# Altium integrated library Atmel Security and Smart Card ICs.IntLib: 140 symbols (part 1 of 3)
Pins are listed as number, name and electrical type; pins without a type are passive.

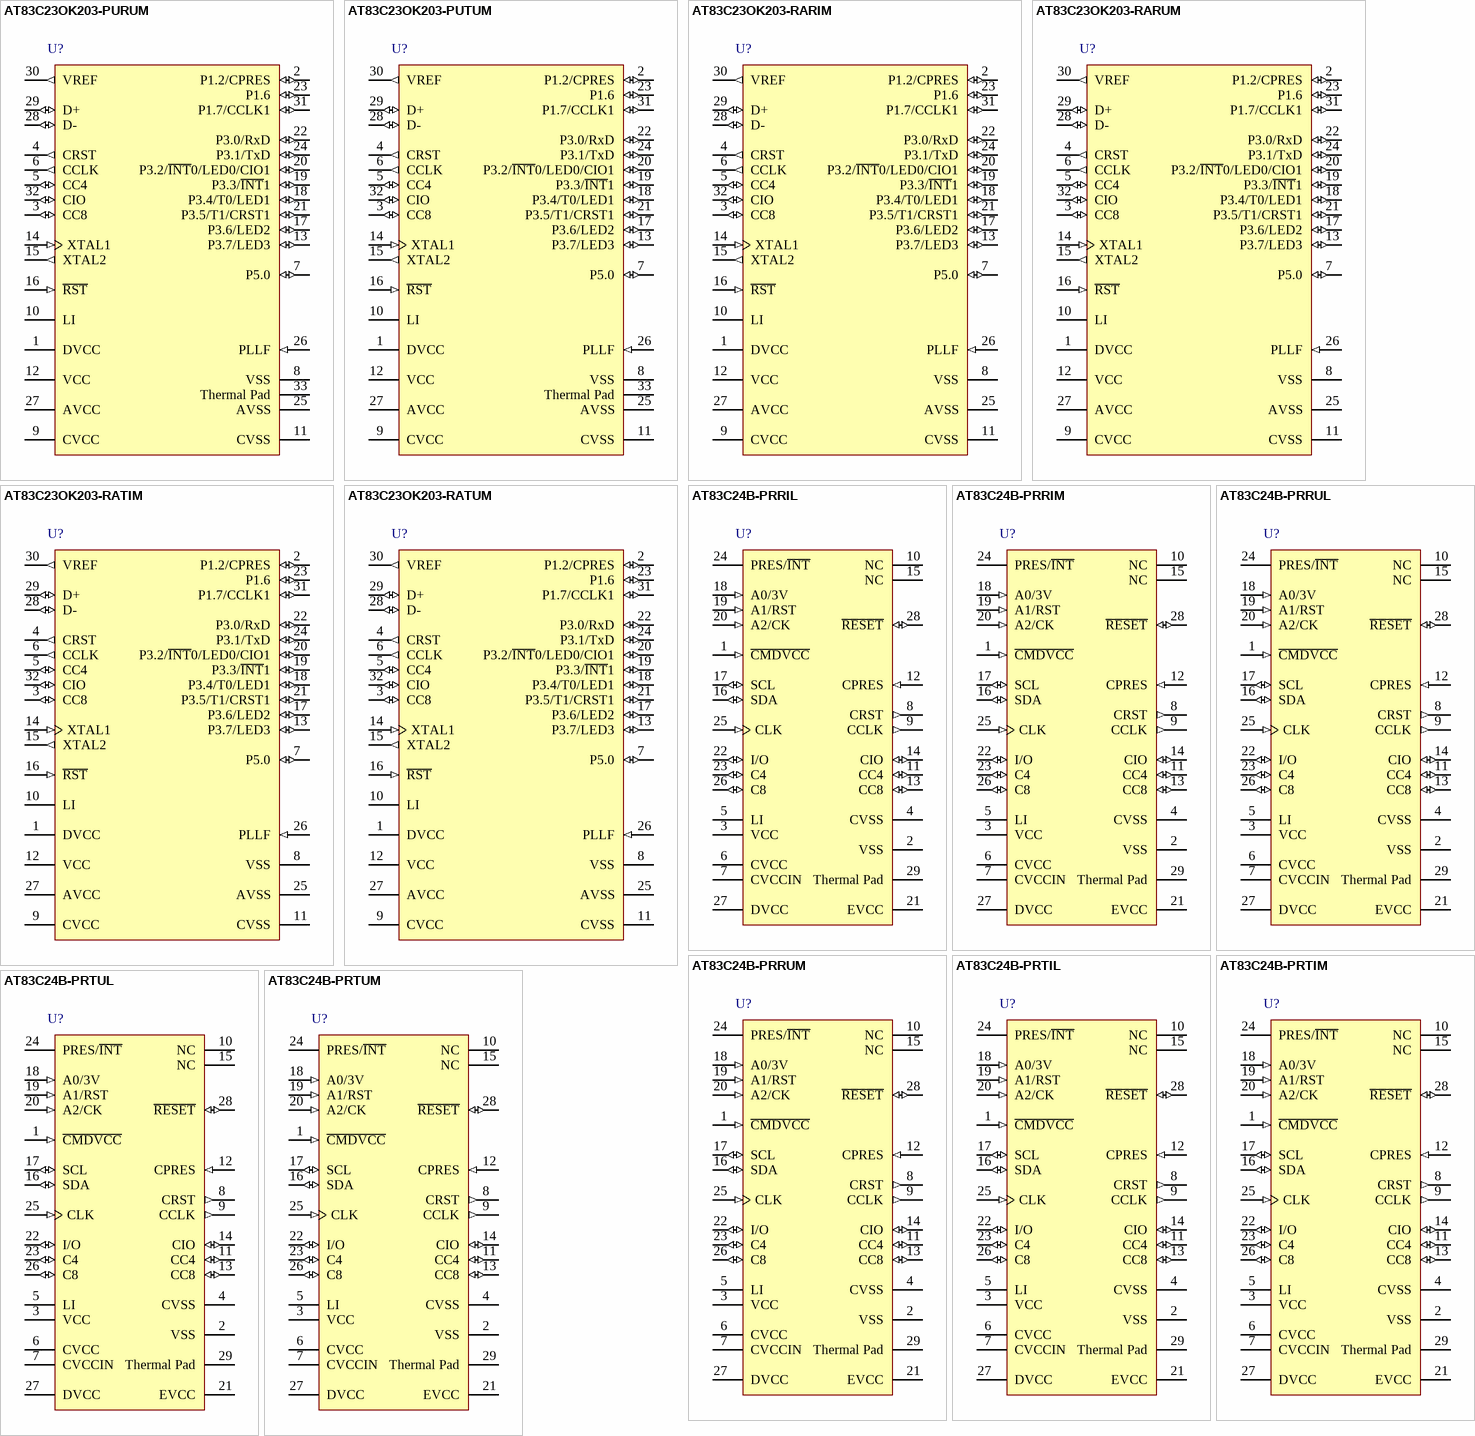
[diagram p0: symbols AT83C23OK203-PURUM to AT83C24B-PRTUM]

## AT83C23OK203-PURUM
designator U?
CardMan® Smart@Link Smart Card Interface, 32-Pin QFN Pkg, Industrial, Tape and Reel, Pb-Free
footprint QFN32_N (QFN, 32-Leads, Body 7x7 mm, Pitch 0.65mm, IPC Medium Density)
footprint QFN32_L (QFN, 32-Leads, Body 7x7 mm, Pitch 0.65mm, IPC High Density)
footprint QFN32_M (QFN, 32-Leads, Body 7x7 mm, Pitch 0.65mm, IPC Low Density)
pins: 1 DVCC (power), 2 P1.2/CPRES (io), 3 CC8 (io), 4 CRST (out), 5 CC4 (io), 6 CCLK (out), 7 P5.0 (io), 8 VSS (power), 9 CVCC (power), 10 LI (power), 11 CVSS (power), 12 VCC (power), 13 P3.7/LED3 (io), 14 XTAL1 (in), 15 XTAL2 (out), 16 ~{RST} (in), 17 P3.6/LED2 (io), 18 P3.4/T0/LED1 (io), 19 P3.3/~{INT}1 (io), 20 P3.2/~{INT}0/LED0/CIO1 (io), 21 P3.5/T1/CRST1 (io), 22 P3.0/RxD (io), 23 P1.6 (io), 24 P3.1/TxD (io), 25 AVSS (power), 26 PLLF (in), 27 AVCC (power), 28 D- (io), 29 D+ (io), 30 VREF (out), 31 P1.7/CCLK1 (io), 32 CIO (io), 33 Thermal Pad (power)

## AT83C23OK203-PUTUM
designator U?
CardMan® Smart@Link Smart Card Interface, 32-Pin QFN Pkg, Industrial, Tray, Pb-Free
footprint QFN32_N (QFN, 32-Leads, Body 7x7 mm, Pitch 0.65mm, IPC Medium Density)
footprint QFN32_L (QFN, 32-Leads, Body 7x7 mm, Pitch 0.65mm, IPC High Density)
footprint QFN32_M (QFN, 32-Leads, Body 7x7 mm, Pitch 0.65mm, IPC Low Density)
pins: 1 DVCC (power), 2 P1.2/CPRES (io), 3 CC8 (io), 4 CRST (out), 5 CC4 (io), 6 CCLK (out), 7 P5.0 (io), 8 VSS (power), 9 CVCC (power), 10 LI (power), 11 CVSS (power), 12 VCC (power), 13 P3.7/LED3 (io), 14 XTAL1 (in), 15 XTAL2 (out), 16 ~{RST} (in), 17 P3.6/LED2 (io), 18 P3.4/T0/LED1 (io), 19 P3.3/~{INT}1 (io), 20 P3.2/~{INT}0/LED0/CIO1 (io), 21 P3.5/T1/CRST1 (io), 22 P3.0/RxD (io), 23 P1.6 (io), 24 P3.1/TxD (io), 25 AVSS (power), 26 PLLF (in), 27 AVCC (power), 28 D- (io), 29 D+ (io), 30 VREF (out), 31 P1.7/CCLK1 (io), 32 CIO (io), 33 Thermal Pad (power)

## AT83C23OK203-RARIM
designator U?
CardMan® Smart@Link Smart Card Interface, 32-Pin QFP Pkg, Industrial, Tape and Reel
footprint LQFP32_N (Thin QFP, 32-Leads, Body 7x7mm, Pitch 0.8mm, IPC Medium Density)
footprint LQFP32_L (Thin QFP, 32-Leads, Body 7x7mm, Pitch 0.8mm, IPC High Density)
footprint LQFP32_M (Thin QFP, 32-Leads, Body 7x7mm, Pitch 0.8mm, IPC Low Density)
pins: 1 DVCC (power), 2 P1.2/CPRES (io), 3 CC8 (io), 4 CRST (out), 5 CC4 (io), 6 CCLK (out), 7 P5.0 (io), 8 VSS (power), 9 CVCC (power), 10 LI (power), 11 CVSS (power), 12 VCC (power), 13 P3.7/LED3 (io), 14 XTAL1 (in), 15 XTAL2 (out), 16 ~{RST} (in), 17 P3.6/LED2 (io), 18 P3.4/T0/LED1 (io), 19 P3.3/~{INT}1 (io), 20 P3.2/~{INT}0/LED0/CIO1 (io), 21 P3.5/T1/CRST1 (io), 22 P3.0/RxD (io), 23 P1.6 (io), 24 P3.1/TxD (io), 25 AVSS (power), 26 PLLF (in), 27 AVCC (power), 28 D- (io), 29 D+ (io), 30 VREF (out), 31 P1.7/CCLK1 (io), 32 CIO (io)

## AT83C23OK203-RARUM
designator U?
CardMan® Smart@Link Smart Card Interface, 32-Pin QFP Pkg, Industrial, Tape and Reel, Pb-Free
footprint LQFP32_N (Thin QFP, 32-Leads, Body 7x7mm, Pitch 0.8mm, IPC Medium Density)
footprint LQFP32_L (Thin QFP, 32-Leads, Body 7x7mm, Pitch 0.8mm, IPC High Density)
footprint LQFP32_M (Thin QFP, 32-Leads, Body 7x7mm, Pitch 0.8mm, IPC Low Density)
pins: 1 DVCC (power), 2 P1.2/CPRES (io), 3 CC8 (io), 4 CRST (out), 5 CC4 (io), 6 CCLK (out), 7 P5.0 (io), 8 VSS (power), 9 CVCC (power), 10 LI (power), 11 CVSS (power), 12 VCC (power), 13 P3.7/LED3 (io), 14 XTAL1 (in), 15 XTAL2 (out), 16 ~{RST} (in), 17 P3.6/LED2 (io), 18 P3.4/T0/LED1 (io), 19 P3.3/~{INT}1 (io), 20 P3.2/~{INT}0/LED0/CIO1 (io), 21 P3.5/T1/CRST1 (io), 22 P3.0/RxD (io), 23 P1.6 (io), 24 P3.1/TxD (io), 25 AVSS (power), 26 PLLF (in), 27 AVCC (power), 28 D- (io), 29 D+ (io), 30 VREF (out), 31 P1.7/CCLK1 (io), 32 CIO (io)

## AT83C23OK203-RATIM
designator U?
CardMan® Smart@Link Smart Card Interface, 32-Pin QFP Pkg, Industrial, Tray
footprint LQFP32_N (Thin QFP, 32-Leads, Body 7x7mm, Pitch 0.8mm, IPC Medium Density)
footprint LQFP32_L (Thin QFP, 32-Leads, Body 7x7mm, Pitch 0.8mm, IPC High Density)
footprint LQFP32_M (Thin QFP, 32-Leads, Body 7x7mm, Pitch 0.8mm, IPC Low Density)
pins: 1 DVCC (power), 2 P1.2/CPRES (io), 3 CC8 (io), 4 CRST (out), 5 CC4 (io), 6 CCLK (out), 7 P5.0 (io), 8 VSS (power), 9 CVCC (power), 10 LI (power), 11 CVSS (power), 12 VCC (power), 13 P3.7/LED3 (io), 14 XTAL1 (in), 15 XTAL2 (out), 16 ~{RST} (in), 17 P3.6/LED2 (io), 18 P3.4/T0/LED1 (io), 19 P3.3/~{INT}1 (io), 20 P3.2/~{INT}0/LED0/CIO1 (io), 21 P3.5/T1/CRST1 (io), 22 P3.0/RxD (io), 23 P1.6 (io), 24 P3.1/TxD (io), 25 AVSS (power), 26 PLLF (in), 27 AVCC (power), 28 D- (io), 29 D+ (io), 30 VREF (out), 31 P1.7/CCLK1 (io), 32 CIO (io)

## AT83C23OK203-RATUM
designator U?
CardMan® Smart@Link Smart Card Interface, 32-Pin QFP Pkg, Industrial, Tray, Pb-Free
footprint LQFP32_N (Thin QFP, 32-Leads, Body 7x7mm, Pitch 0.8mm, IPC Medium Density)
footprint LQFP32_L (Thin QFP, 32-Leads, Body 7x7mm, Pitch 0.8mm, IPC High Density)
footprint LQFP32_M (Thin QFP, 32-Leads, Body 7x7mm, Pitch 0.8mm, IPC Low Density)
pins: 1 DVCC (power), 2 P1.2/CPRES (io), 3 CC8 (io), 4 CRST (out), 5 CC4 (io), 6 CCLK (out), 7 P5.0 (io), 8 VSS (power), 9 CVCC (power), 10 LI (power), 11 CVSS (power), 12 VCC (power), 13 P3.7/LED3 (io), 14 XTAL1 (in), 15 XTAL2 (out), 16 ~{RST} (in), 17 P3.6/LED2 (io), 18 P3.4/T0/LED1 (io), 19 P3.3/~{INT}1 (io), 20 P3.2/~{INT}0/LED0/CIO1 (io), 21 P3.5/T1/CRST1 (io), 22 P3.0/RxD (io), 23 P1.6 (io), 24 P3.1/TxD (io), 25 AVSS (power), 26 PLLF (in), 27 AVCC (power), 28 D- (io), 29 D+ (io), 30 VREF (out), 31 P1.7/CCLK1 (io), 32 CIO (io)

## AT83C24B-PRRIL
designator U?
Smart Card Reader Interface with Power Management, 3V to 5.5V, 28-Pin QFN Pkg, Industrial, Tape and Reel
footprint QFN28 (QFN, 28-Leads, Body 5x5mm, Pitch 0.5mm, NSC Recommended)
pins: 1 ~{CMDVCC} (in), 2 VSS (power), 3 VCC (power), 4 CVSS (power), 5 LI (power), 6 CVCC (power), 7 CVCCIN (power), 8 CRST (out), 9 CCLK (out), 10 NC, 11 CC4 (io), 12 CPRES (in), 13 CC8 (io), 14 CIO (io), 15 NC, 16 SDA (io), 17 SCL (io), 18 A0/3V (in), 19 A1/RST (in), 20 A2/CK (in), 21 EVCC (power), 22 I/O (io), 23 C4 (io), 24 PRES/~{INT} (oc), 25 CLK (in), 26 C8 (io), 27 DVCC (power), 28 ~{RESET} (io), 29 Thermal Pad (power)

## AT83C24B-PRRIM
designator U?
Smart Card Reader Interface with Power Management, 4V to 5.5V, 28-Pin QFN Pkg, Industrial, Tape and Reel
footprint QFN28 (QFN, 28-Leads, Body 5x5mm, Pitch 0.5mm, NSC Recommended)
pins: 1 ~{CMDVCC} (in), 2 VSS (power), 3 VCC (power), 4 CVSS (power), 5 LI (power), 6 CVCC (power), 7 CVCCIN (power), 8 CRST (out), 9 CCLK (out), 10 NC, 11 CC4 (io), 12 CPRES (in), 13 CC8 (io), 14 CIO (io), 15 NC, 16 SDA (io), 17 SCL (io), 18 A0/3V (in), 19 A1/RST (in), 20 A2/CK (in), 21 EVCC (power), 22 I/O (io), 23 C4 (io), 24 PRES/~{INT} (oc), 25 CLK (in), 26 C8 (io), 27 DVCC (power), 28 ~{RESET} (io), 29 Thermal Pad (power)

## AT83C24B-PRRUL
designator U?
Smart Card Reader Interface with Power Management, 3V to 5.5V, 28-Pin QFN Pkg, Industrial, Tape and Reel, Pb-Free
footprint QFN28 (QFN, 28-Leads, Body 5x5mm, Pitch 0.5mm, NSC Recommended)
pins: 1 ~{CMDVCC} (in), 2 VSS (power), 3 VCC (power), 4 CVSS (power), 5 LI (power), 6 CVCC (power), 7 CVCCIN (power), 8 CRST (out), 9 CCLK (out), 10 NC, 11 CC4 (io), 12 CPRES (in), 13 CC8 (io), 14 CIO (io), 15 NC, 16 SDA (io), 17 SCL (io), 18 A0/3V (in), 19 A1/RST (in), 20 A2/CK (in), 21 EVCC (power), 22 I/O (io), 23 C4 (io), 24 PRES/~{INT} (oc), 25 CLK (in), 26 C8 (io), 27 DVCC (power), 28 ~{RESET} (io), 29 Thermal Pad (power)

## AT83C24B-PRRUM
designator U?
Smart Card Reader Interface with Power Management, 4V to 5.5V, 28-Pin QFN Pkg, Industrial, Tape and Reel, Pb-Free
footprint QFN28 (QFN, 28-Leads, Body 5x5mm, Pitch 0.5mm, NSC Recommended)
pins: 1 ~{CMDVCC} (in), 2 VSS (power), 3 VCC (power), 4 CVSS (power), 5 LI (power), 6 CVCC (power), 7 CVCCIN (power), 8 CRST (out), 9 CCLK (out), 10 NC, 11 CC4 (io), 12 CPRES (in), 13 CC8 (io), 14 CIO (io), 15 NC, 16 SDA (io), 17 SCL (io), 18 A0/3V (in), 19 A1/RST (in), 20 A2/CK (in), 21 EVCC (power), 22 I/O (io), 23 C4 (io), 24 PRES/~{INT} (oc), 25 CLK (in), 26 C8 (io), 27 DVCC (power), 28 ~{RESET} (io), 29 Thermal Pad (power)

## AT83C24B-PRTIL
designator U?
Smart Card Reader Interface with Power Management, 3V to 5.5V, 28-Pin QFN Pkg, Industrial, Tray
footprint QFN28 (QFN, 28-Leads, Body 5x5mm, Pitch 0.5mm, NSC Recommended)
pins: 1 ~{CMDVCC} (in), 2 VSS (power), 3 VCC (power), 4 CVSS (power), 5 LI (power), 6 CVCC (power), 7 CVCCIN (power), 8 CRST (out), 9 CCLK (out), 10 NC, 11 CC4 (io), 12 CPRES (in), 13 CC8 (io), 14 CIO (io), 15 NC, 16 SDA (io), 17 SCL (io), 18 A0/3V (in), 19 A1/RST (in), 20 A2/CK (in), 21 EVCC (power), 22 I/O (io), 23 C4 (io), 24 PRES/~{INT} (oc), 25 CLK (in), 26 C8 (io), 27 DVCC (power), 28 ~{RESET} (io), 29 Thermal Pad (power)

## AT83C24B-PRTIM
designator U?
Smart Card Reader Interface with Power Management, 4V to 5.5V, 28-Pin QFN Pkg, Industrial, Tray
footprint QFN28 (QFN, 28-Leads, Body 5x5mm, Pitch 0.5mm, NSC Recommended)
pins: 1 ~{CMDVCC} (in), 2 VSS (power), 3 VCC (power), 4 CVSS (power), 5 LI (power), 6 CVCC (power), 7 CVCCIN (power), 8 CRST (out), 9 CCLK (out), 10 NC, 11 CC4 (io), 12 CPRES (in), 13 CC8 (io), 14 CIO (io), 15 NC, 16 SDA (io), 17 SCL (io), 18 A0/3V (in), 19 A1/RST (in), 20 A2/CK (in), 21 EVCC (power), 22 I/O (io), 23 C4 (io), 24 PRES/~{INT} (oc), 25 CLK (in), 26 C8 (io), 27 DVCC (power), 28 ~{RESET} (io), 29 Thermal Pad (power)

## AT83C24B-PRTUL
designator U?
Smart Card Reader Interface with Power Management, 3V to 5.5V, 28-Pin QFN Pkg, Industrial, Tray, Pb-Free
footprint QFN28 (QFN, 28-Leads, Body 5x5mm, Pitch 0.5mm, NSC Recommended)
pins: 1 ~{CMDVCC} (in), 2 VSS (power), 3 VCC (power), 4 CVSS (power), 5 LI (power), 6 CVCC (power), 7 CVCCIN (power), 8 CRST (out), 9 CCLK (out), 10 NC, 11 CC4 (io), 12 CPRES (in), 13 CC8 (io), 14 CIO (io), 15 NC, 16 SDA (io), 17 SCL (io), 18 A0/3V (in), 19 A1/RST (in), 20 A2/CK (in), 21 EVCC (power), 22 I/O (io), 23 C4 (io), 24 PRES/~{INT} (oc), 25 CLK (in), 26 C8 (io), 27 DVCC (power), 28 ~{RESET} (io), 29 Thermal Pad (power)

## AT83C24B-PRTUM
designator U?
Smart Card Reader Interface with Power Management, 4V to 5.5V, 28-Pin QFN Pkg, Industrial, Tray, Pb-Free
footprint QFN28 (QFN, 28-Leads, Body 5x5mm, Pitch 0.5mm, NSC Recommended)
pins: 1 ~{CMDVCC} (in), 2 VSS (power), 3 VCC (power), 4 CVSS (power), 5 LI (power), 6 CVCC (power), 7 CVCCIN (power), 8 CRST (out), 9 CCLK (out), 10 NC, 11 CC4 (io), 12 CPRES (in), 13 CC8 (io), 14 CIO (io), 15 NC, 16 SDA (io), 17 SCL (io), 18 A0/3V (in), 19 A1/RST (in), 20 A2/CK (in), 21 EVCC (power), 22 I/O (io), 23 C4 (io), 24 PRES/~{INT} (oc), 25 CLK (in), 26 C8 (io), 27 DVCC (power), 28 ~{RESET} (io), 29 Thermal Pad (power)

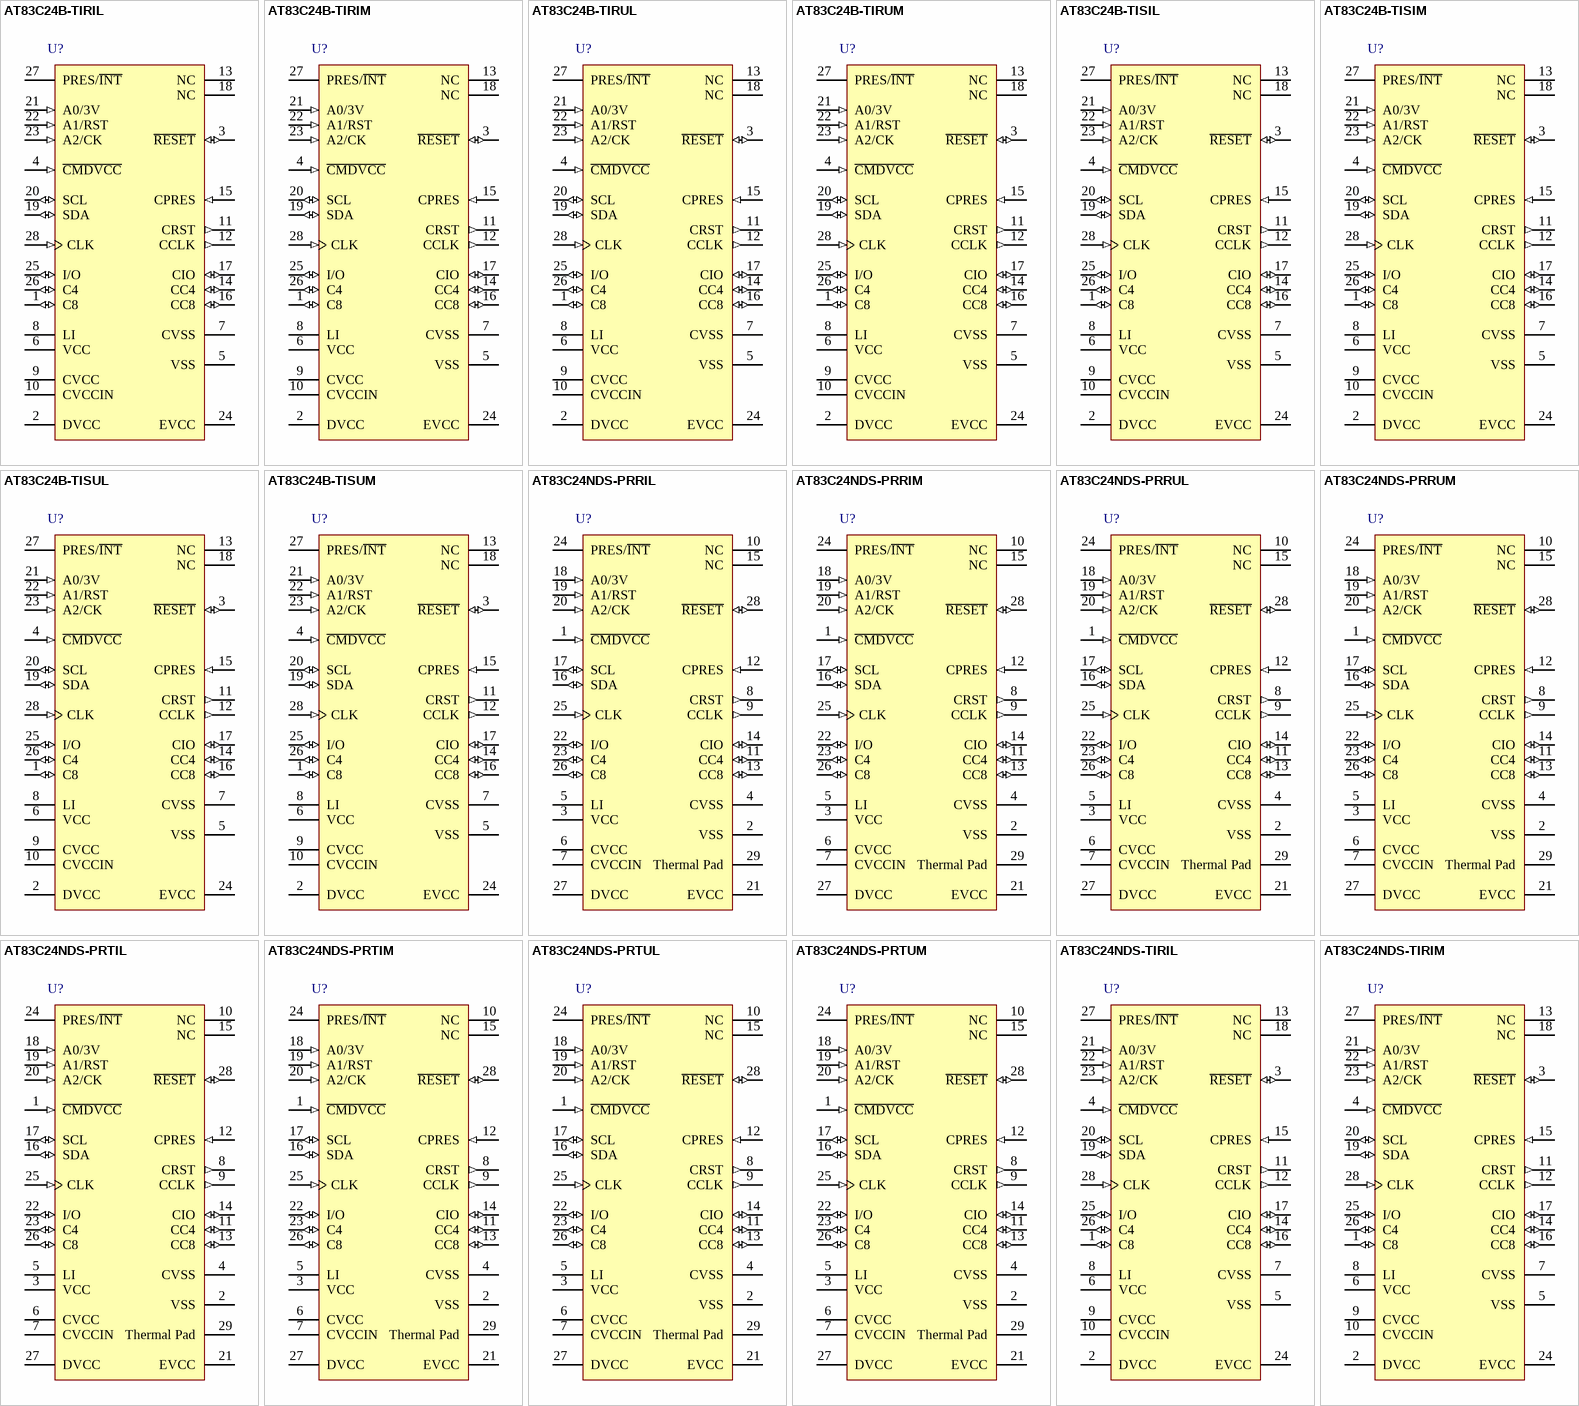
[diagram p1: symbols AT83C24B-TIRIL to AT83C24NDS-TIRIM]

## AT83C24B-TIRIL
designator U?
Smart Card Reader Interface with Power Management, 3V to 5.5V, 28-Pin SOIC Pkg, Industrial, Tape and Reel
footprint SO28_N (SOIC, 28-Leads, Body 17.9x7.5mm, Pitch 1.27mm, IPC Medium Density)
footprint SO28_L (SOIC, 28-Leads, Body 17.9x7.5mm, Pitch 1.27mm, IPC High Density)
footprint SO28_M (SOIC, 28-Leads, Body 17.9x7.5mm, Pitch 1.27mm, IPC Low Density)
pins: 1 C8 (io), 2 DVCC (power), 3 ~{RESET} (io), 4 ~{CMDVCC} (in), 5 VSS (power), 6 VCC (power), 7 CVSS (power), 8 LI (power), 9 CVCC (power), 10 CVCCIN (power), 11 CRST (out), 12 CCLK (out), 13 NC, 14 CC4 (io), 15 CPRES (in), 16 CC8 (io), 17 CIO (io), 18 NC, 19 SDA (io), 20 SCL (io), 21 A0/3V (in), 22 A1/RST (in), 23 A2/CK (in), 24 EVCC (power), 25 I/O (io), 26 C4 (io), 27 PRES/~{INT} (oc), 28 CLK (in)

## AT83C24B-TIRIM
designator U?
Smart Card Reader Interface with Power Management, 4V to 5.5V, 28-Pin SOIC Pkg, Industrial, Tape and Reel
footprint SO28_N (SOIC, 28-Leads, Body 17.9x7.5mm, Pitch 1.27mm, IPC Medium Density)
footprint SO28_L (SOIC, 28-Leads, Body 17.9x7.5mm, Pitch 1.27mm, IPC High Density)
footprint SO28_M (SOIC, 28-Leads, Body 17.9x7.5mm, Pitch 1.27mm, IPC Low Density)
pins: 1 C8 (io), 2 DVCC (power), 3 ~{RESET} (io), 4 ~{CMDVCC} (in), 5 VSS (power), 6 VCC (power), 7 CVSS (power), 8 LI (power), 9 CVCC (power), 10 CVCCIN (power), 11 CRST (out), 12 CCLK (out), 13 NC, 14 CC4 (io), 15 CPRES (in), 16 CC8 (io), 17 CIO (io), 18 NC, 19 SDA (io), 20 SCL (io), 21 A0/3V (in), 22 A1/RST (in), 23 A2/CK (in), 24 EVCC (power), 25 I/O (io), 26 C4 (io), 27 PRES/~{INT} (oc), 28 CLK (in)

## AT83C24B-TIRUL
designator U?
Smart Card Reader Interface with Power Management, 3V to 5.5V, 28-Pin SOIC Pkg, Industrial, Tape and Reel, Pb-Free
footprint SO28_N (SOIC, 28-Leads, Body 17.9x7.5mm, Pitch 1.27mm, IPC Medium Density)
footprint SO28_L (SOIC, 28-Leads, Body 17.9x7.5mm, Pitch 1.27mm, IPC High Density)
footprint SO28_M (SOIC, 28-Leads, Body 17.9x7.5mm, Pitch 1.27mm, IPC Low Density)
pins: 1 C8 (io), 2 DVCC (power), 3 ~{RESET} (io), 4 ~{CMDVCC} (in), 5 VSS (power), 6 VCC (power), 7 CVSS (power), 8 LI (power), 9 CVCC (power), 10 CVCCIN (power), 11 CRST (out), 12 CCLK (out), 13 NC, 14 CC4 (io), 15 CPRES (in), 16 CC8 (io), 17 CIO (io), 18 NC, 19 SDA (io), 20 SCL (io), 21 A0/3V (in), 22 A1/RST (in), 23 A2/CK (in), 24 EVCC (power), 25 I/O (io), 26 C4 (io), 27 PRES/~{INT} (oc), 28 CLK (in)

## AT83C24B-TIRUM
designator U?
Smart Card Reader Interface with Power Management, 4V to 5.5V, 28-Pin SOIC Pkg, Industrial, Tape and Reel, Pb-Free
footprint SO28_N (SOIC, 28-Leads, Body 17.9x7.5mm, Pitch 1.27mm, IPC Medium Density)
footprint SO28_L (SOIC, 28-Leads, Body 17.9x7.5mm, Pitch 1.27mm, IPC High Density)
footprint SO28_M (SOIC, 28-Leads, Body 17.9x7.5mm, Pitch 1.27mm, IPC Low Density)
pins: 1 C8 (io), 2 DVCC (power), 3 ~{RESET} (io), 4 ~{CMDVCC} (in), 5 VSS (power), 6 VCC (power), 7 CVSS (power), 8 LI (power), 9 CVCC (power), 10 CVCCIN (power), 11 CRST (out), 12 CCLK (out), 13 NC, 14 CC4 (io), 15 CPRES (in), 16 CC8 (io), 17 CIO (io), 18 NC, 19 SDA (io), 20 SCL (io), 21 A0/3V (in), 22 A1/RST (in), 23 A2/CK (in), 24 EVCC (power), 25 I/O (io), 26 C4 (io), 27 PRES/~{INT} (oc), 28 CLK (in)

## AT83C24B-TISIL
designator U?
Smart Card Reader Interface with Power Management, 3V to 5.5V, 28-Pin SOIC Pkg, Industrial, Stick
footprint SO28_N (SOIC, 28-Leads, Body 17.9x7.5mm, Pitch 1.27mm, IPC Medium Density)
footprint SO28_L (SOIC, 28-Leads, Body 17.9x7.5mm, Pitch 1.27mm, IPC High Density)
footprint SO28_M (SOIC, 28-Leads, Body 17.9x7.5mm, Pitch 1.27mm, IPC Low Density)
pins: 1 C8 (io), 2 DVCC (power), 3 ~{RESET} (io), 4 ~{CMDVCC} (in), 5 VSS (power), 6 VCC (power), 7 CVSS (power), 8 LI (power), 9 CVCC (power), 10 CVCCIN (power), 11 CRST (out), 12 CCLK (out), 13 NC, 14 CC4 (io), 15 CPRES (in), 16 CC8 (io), 17 CIO (io), 18 NC, 19 SDA (io), 20 SCL (io), 21 A0/3V (in), 22 A1/RST (in), 23 A2/CK (in), 24 EVCC (power), 25 I/O (io), 26 C4 (io), 27 PRES/~{INT} (oc), 28 CLK (in)

## AT83C24B-TISIM
designator U?
Smart Card Reader Interface with Power Management, 4V to 5.5V, 28-Pin SOIC Pkg, Industrial, Stick
footprint SO28_N (SOIC, 28-Leads, Body 17.9x7.5mm, Pitch 1.27mm, IPC Medium Density)
footprint SO28_L (SOIC, 28-Leads, Body 17.9x7.5mm, Pitch 1.27mm, IPC High Density)
footprint SO28_M (SOIC, 28-Leads, Body 17.9x7.5mm, Pitch 1.27mm, IPC Low Density)
pins: 1 C8 (io), 2 DVCC (power), 3 ~{RESET} (io), 4 ~{CMDVCC} (in), 5 VSS (power), 6 VCC (power), 7 CVSS (power), 8 LI (power), 9 CVCC (power), 10 CVCCIN (power), 11 CRST (out), 12 CCLK (out), 13 NC, 14 CC4 (io), 15 CPRES (in), 16 CC8 (io), 17 CIO (io), 18 NC, 19 SDA (io), 20 SCL (io), 21 A0/3V (in), 22 A1/RST (in), 23 A2/CK (in), 24 EVCC (power), 25 I/O (io), 26 C4 (io), 27 PRES/~{INT} (oc), 28 CLK (in)

## AT83C24B-TISUL
designator U?
Smart Card Reader Interface with Power Management, 3V to 5.5V, 28-Pin SOIC Pkg, Industrial, Stick, Pb-Free
footprint SO28_N (SOIC, 28-Leads, Body 17.9x7.5mm, Pitch 1.27mm, IPC Medium Density)
footprint SO28_L (SOIC, 28-Leads, Body 17.9x7.5mm, Pitch 1.27mm, IPC High Density)
footprint SO28_M (SOIC, 28-Leads, Body 17.9x7.5mm, Pitch 1.27mm, IPC Low Density)
pins: 1 C8 (io), 2 DVCC (power), 3 ~{RESET} (io), 4 ~{CMDVCC} (in), 5 VSS (power), 6 VCC (power), 7 CVSS (power), 8 LI (power), 9 CVCC (power), 10 CVCCIN (power), 11 CRST (out), 12 CCLK (out), 13 NC, 14 CC4 (io), 15 CPRES (in), 16 CC8 (io), 17 CIO (io), 18 NC, 19 SDA (io), 20 SCL (io), 21 A0/3V (in), 22 A1/RST (in), 23 A2/CK (in), 24 EVCC (power), 25 I/O (io), 26 C4 (io), 27 PRES/~{INT} (oc), 28 CLK (in)

## AT83C24B-TISUM
designator U?
Smart Card Reader Interface with Power Management, 4V to 5.5V, 28-Pin SOIC Pkg, Industrial, Stick, Pb-Free
footprint SO28_N (SOIC, 28-Leads, Body 17.9x7.5mm, Pitch 1.27mm, IPC Medium Density)
footprint SO28_L (SOIC, 28-Leads, Body 17.9x7.5mm, Pitch 1.27mm, IPC High Density)
footprint SO28_M (SOIC, 28-Leads, Body 17.9x7.5mm, Pitch 1.27mm, IPC Low Density)
pins: 1 C8 (io), 2 DVCC (power), 3 ~{RESET} (io), 4 ~{CMDVCC} (in), 5 VSS (power), 6 VCC (power), 7 CVSS (power), 8 LI (power), 9 CVCC (power), 10 CVCCIN (power), 11 CRST (out), 12 CCLK (out), 13 NC, 14 CC4 (io), 15 CPRES (in), 16 CC8 (io), 17 CIO (io), 18 NC, 19 SDA (io), 20 SCL (io), 21 A0/3V (in), 22 A1/RST (in), 23 A2/CK (in), 24 EVCC (power), 25 I/O (io), 26 C4 (io), 27 PRES/~{INT} (oc), 28 CLK (in)

## AT83C24NDS-PRRIL
designator U?
Smart Card Reader Interface with Power Management, 3V to 5.5V, 28-Pin QFN Pkg, Industrial, Tape and Reel
footprint QFN28 (QFN, 28-Leads, Body 5x5mm, Pitch 0.5mm, NSC Recommended)
pins: 1 ~{CMDVCC} (in), 2 VSS (power), 3 VCC (power), 4 CVSS (power), 5 LI (power), 6 CVCC (power), 7 CVCCIN (power), 8 CRST (out), 9 CCLK (out), 10 NC, 11 CC4 (io), 12 CPRES (in), 13 CC8 (io), 14 CIO (io), 15 NC, 16 SDA (io), 17 SCL (io), 18 A0/3V (in), 19 A1/RST (in), 20 A2/CK (in), 21 EVCC (power), 22 I/O (io), 23 C4 (io), 24 PRES/~{INT} (oc), 25 CLK (in), 26 C8 (io), 27 DVCC (power), 28 ~{RESET} (io), 29 Thermal Pad (power)

## AT83C24NDS-PRRIM
designator U?
Smart Card Reader Interface with Power Management, 4V to 5.5V, 28-Pin QFN Pkg, Industrial, Tape and Reel
footprint QFN28 (QFN, 28-Leads, Body 5x5mm, Pitch 0.5mm, NSC Recommended)
pins: 1 ~{CMDVCC} (in), 2 VSS (power), 3 VCC (power), 4 CVSS (power), 5 LI (power), 6 CVCC (power), 7 CVCCIN (power), 8 CRST (out), 9 CCLK (out), 10 NC, 11 CC4 (io), 12 CPRES (in), 13 CC8 (io), 14 CIO (io), 15 NC, 16 SDA (io), 17 SCL (io), 18 A0/3V (in), 19 A1/RST (in), 20 A2/CK (in), 21 EVCC (power), 22 I/O (io), 23 C4 (io), 24 PRES/~{INT} (oc), 25 CLK (in), 26 C8 (io), 27 DVCC (power), 28 ~{RESET} (io), 29 Thermal Pad (power)

## AT83C24NDS-PRRUL
designator U?
Smart Card Reader Interface with Power Management, 3V to 5.5V, 28-Pin QFN Pkg, Industrial, Tape and Reel, Pb-Free
footprint QFN28 (QFN, 28-Leads, Body 5x5mm, Pitch 0.5mm, NSC Recommended)
pins: 1 ~{CMDVCC} (in), 2 VSS (power), 3 VCC (power), 4 CVSS (power), 5 LI (power), 6 CVCC (power), 7 CVCCIN (power), 8 CRST (out), 9 CCLK (out), 10 NC, 11 CC4 (io), 12 CPRES (in), 13 CC8 (io), 14 CIO (io), 15 NC, 16 SDA (io), 17 SCL (io), 18 A0/3V (in), 19 A1/RST (in), 20 A2/CK (in), 21 EVCC (power), 22 I/O (io), 23 C4 (io), 24 PRES/~{INT} (oc), 25 CLK (in), 26 C8 (io), 27 DVCC (power), 28 ~{RESET} (io), 29 Thermal Pad (power)

## AT83C24NDS-PRRUM
designator U?
Smart Card Reader Interface with Power Management, 4V to 5.5V, 28-Pin QFN Pkg, Industrial, Tape and Reel, Pb-Free
footprint QFN28 (QFN, 28-Leads, Body 5x5mm, Pitch 0.5mm, NSC Recommended)
pins: 1 ~{CMDVCC} (in), 2 VSS (power), 3 VCC (power), 4 CVSS (power), 5 LI (power), 6 CVCC (power), 7 CVCCIN (power), 8 CRST (out), 9 CCLK (out), 10 NC, 11 CC4 (io), 12 CPRES (in), 13 CC8 (io), 14 CIO (io), 15 NC, 16 SDA (io), 17 SCL (io), 18 A0/3V (in), 19 A1/RST (in), 20 A2/CK (in), 21 EVCC (power), 22 I/O (io), 23 C4 (io), 24 PRES/~{INT} (oc), 25 CLK (in), 26 C8 (io), 27 DVCC (power), 28 ~{RESET} (io), 29 Thermal Pad (power)

## AT83C24NDS-PRTIL
designator U?
Smart Card Reader Interface with Power Management, 3V to 5.5V, 28-Pin QFN Pkg, Industrial, Tray
footprint QFN28 (QFN, 28-Leads, Body 5x5mm, Pitch 0.5mm, NSC Recommended)
pins: 1 ~{CMDVCC} (in), 2 VSS (power), 3 VCC (power), 4 CVSS (power), 5 LI (power), 6 CVCC (power), 7 CVCCIN (power), 8 CRST (out), 9 CCLK (out), 10 NC, 11 CC4 (io), 12 CPRES (in), 13 CC8 (io), 14 CIO (io), 15 NC, 16 SDA (io), 17 SCL (io), 18 A0/3V (in), 19 A1/RST (in), 20 A2/CK (in), 21 EVCC (power), 22 I/O (io), 23 C4 (io), 24 PRES/~{INT} (oc), 25 CLK (in), 26 C8 (io), 27 DVCC (power), 28 ~{RESET} (io), 29 Thermal Pad (power)

## AT83C24NDS-PRTIM
designator U?
Smart Card Reader Interface with Power Management, 4V to 5.5V, 28-Pin QFN Pkg, Industrial, Tray
footprint QFN28 (QFN, 28-Leads, Body 5x5mm, Pitch 0.5mm, NSC Recommended)
pins: 1 ~{CMDVCC} (in), 2 VSS (power), 3 VCC (power), 4 CVSS (power), 5 LI (power), 6 CVCC (power), 7 CVCCIN (power), 8 CRST (out), 9 CCLK (out), 10 NC, 11 CC4 (io), 12 CPRES (in), 13 CC8 (io), 14 CIO (io), 15 NC, 16 SDA (io), 17 SCL (io), 18 A0/3V (in), 19 A1/RST (in), 20 A2/CK (in), 21 EVCC (power), 22 I/O (io), 23 C4 (io), 24 PRES/~{INT} (oc), 25 CLK (in), 26 C8 (io), 27 DVCC (power), 28 ~{RESET} (io), 29 Thermal Pad (power)

## AT83C24NDS-PRTUL
designator U?
Smart Card Reader Interface with Power Management, 3V to 5.5V, 28-Pin QFN Pkg, Industrial, Tray, Pb-Free
footprint QFN28 (QFN, 28-Leads, Body 5x5mm, Pitch 0.5mm, NSC Recommended)
pins: 1 ~{CMDVCC} (in), 2 VSS (power), 3 VCC (power), 4 CVSS (power), 5 LI (power), 6 CVCC (power), 7 CVCCIN (power), 8 CRST (out), 9 CCLK (out), 10 NC, 11 CC4 (io), 12 CPRES (in), 13 CC8 (io), 14 CIO (io), 15 NC, 16 SDA (io), 17 SCL (io), 18 A0/3V (in), 19 A1/RST (in), 20 A2/CK (in), 21 EVCC (power), 22 I/O (io), 23 C4 (io), 24 PRES/~{INT} (oc), 25 CLK (in), 26 C8 (io), 27 DVCC (power), 28 ~{RESET} (io), 29 Thermal Pad (power)

## AT83C24NDS-PRTUM
designator U?
Smart Card Reader Interface with Power Management, 4V to 5.5V, 28-Pin QFN Pkg, Industrial, Tray, Pb-Free
footprint QFN28 (QFN, 28-Leads, Body 5x5mm, Pitch 0.5mm, NSC Recommended)
pins: 1 ~{CMDVCC} (in), 2 VSS (power), 3 VCC (power), 4 CVSS (power), 5 LI (power), 6 CVCC (power), 7 CVCCIN (power), 8 CRST (out), 9 CCLK (out), 10 NC, 11 CC4 (io), 12 CPRES (in), 13 CC8 (io), 14 CIO (io), 15 NC, 16 SDA (io), 17 SCL (io), 18 A0/3V (in), 19 A1/RST (in), 20 A2/CK (in), 21 EVCC (power), 22 I/O (io), 23 C4 (io), 24 PRES/~{INT} (oc), 25 CLK (in), 26 C8 (io), 27 DVCC (power), 28 ~{RESET} (io), 29 Thermal Pad (power)

## AT83C24NDS-TIRIL
designator U?
Smart Card Reader Interface with Power Management, 3V to 5.5V, 28-Pin SOIC Pkg, Industrial, Tape and Reel
footprint SO28_N (SOIC, 28-Leads, Body 17.9x7.5mm, Pitch 1.27mm, IPC Medium Density)
footprint SO28_L (SOIC, 28-Leads, Body 17.9x7.5mm, Pitch 1.27mm, IPC High Density)
footprint SO28_M (SOIC, 28-Leads, Body 17.9x7.5mm, Pitch 1.27mm, IPC Low Density)
pins: 1 C8 (io), 2 DVCC (power), 3 ~{RESET} (io), 4 ~{CMDVCC} (in), 5 VSS (power), 6 VCC (power), 7 CVSS (power), 8 LI (power), 9 CVCC (power), 10 CVCCIN (power), 11 CRST (out), 12 CCLK (out), 13 NC, 14 CC4 (io), 15 CPRES (in), 16 CC8 (io), 17 CIO (io), 18 NC, 19 SDA (io), 20 SCL (io), 21 A0/3V (in), 22 A1/RST (in), 23 A2/CK (in), 24 EVCC (power), 25 I/O (io), 26 C4 (io), 27 PRES/~{INT} (oc), 28 CLK (in)

## AT83C24NDS-TIRIM
designator U?
Smart Card Reader Interface with Power Management, 4V to 5.5V, 28-Pin SOIC Pkg, Industrial, Tape and Reel
footprint SO28_N (SOIC, 28-Leads, Body 17.9x7.5mm, Pitch 1.27mm, IPC Medium Density)
footprint SO28_L (SOIC, 28-Leads, Body 17.9x7.5mm, Pitch 1.27mm, IPC High Density)
footprint SO28_M (SOIC, 28-Leads, Body 17.9x7.5mm, Pitch 1.27mm, IPC Low Density)
pins: 1 C8 (io), 2 DVCC (power), 3 ~{RESET} (io), 4 ~{CMDVCC} (in), 5 VSS (power), 6 VCC (power), 7 CVSS (power), 8 LI (power), 9 CVCC (power), 10 CVCCIN (power), 11 CRST (out), 12 CCLK (out), 13 NC, 14 CC4 (io), 15 CPRES (in), 16 CC8 (io), 17 CIO (io), 18 NC, 19 SDA (io), 20 SCL (io), 21 A0/3V (in), 22 A1/RST (in), 23 A2/CK (in), 24 EVCC (power), 25 I/O (io), 26 C4 (io), 27 PRES/~{INT} (oc), 28 CLK (in)

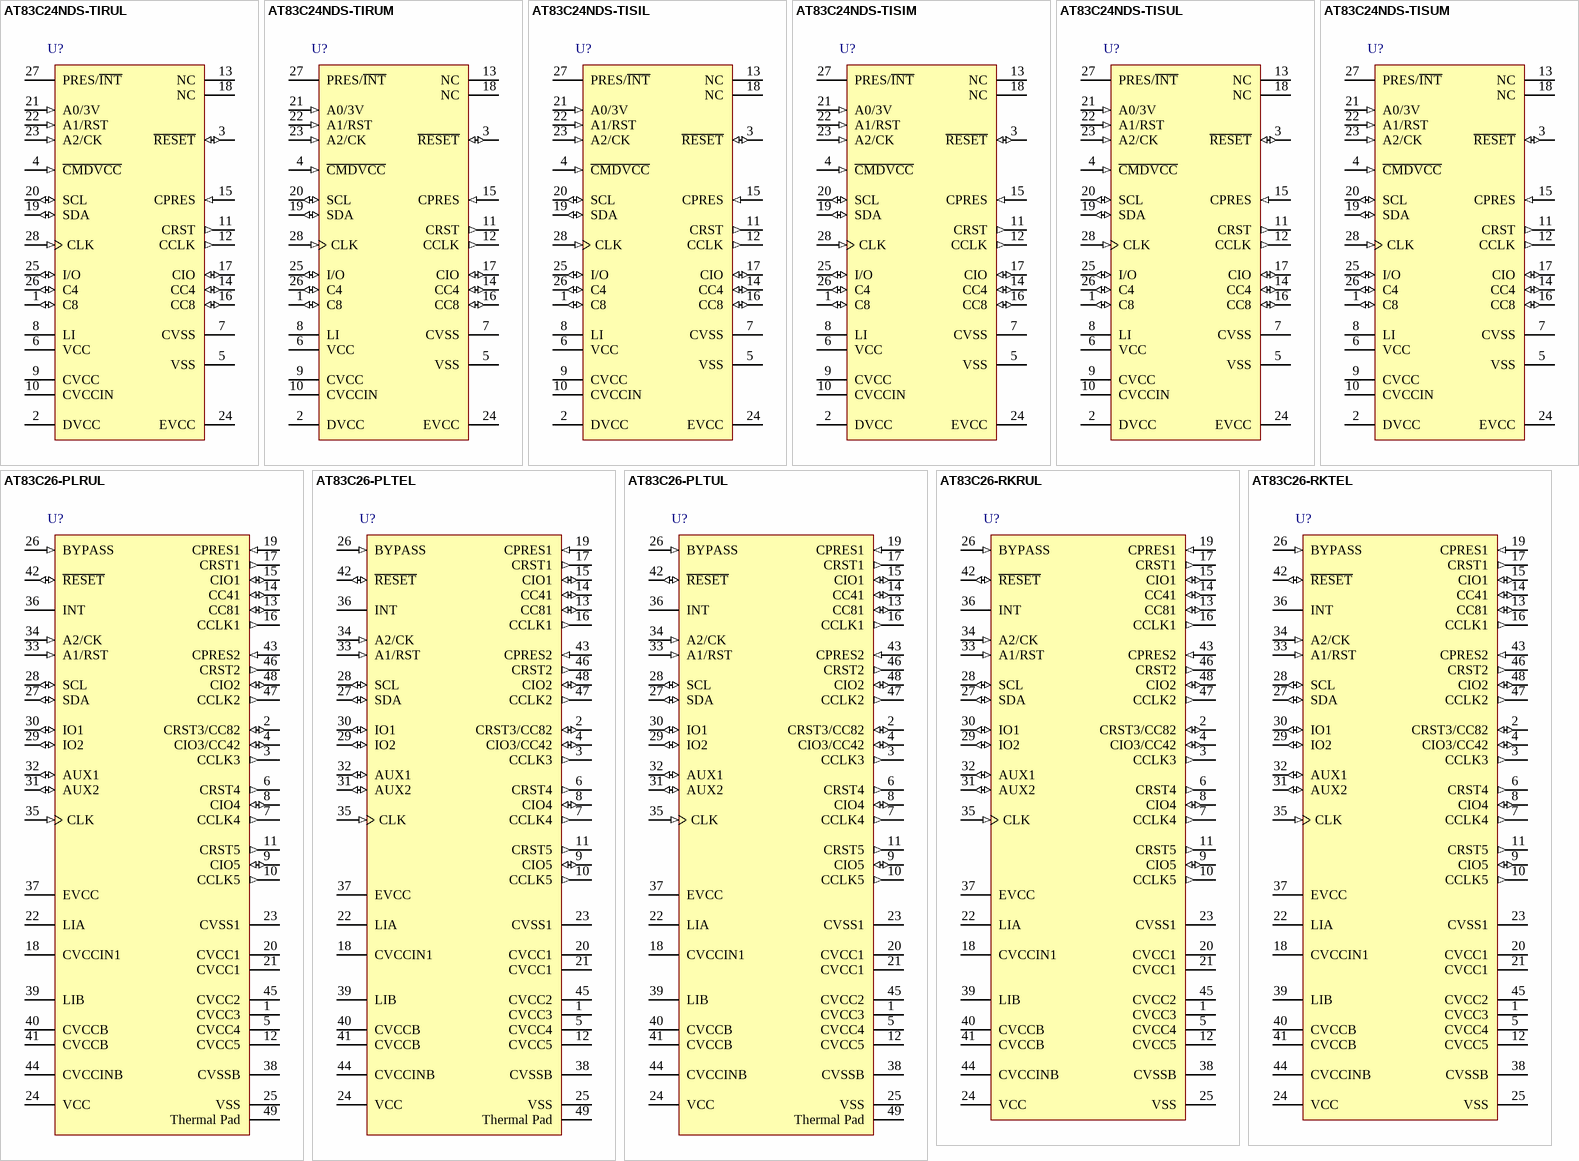
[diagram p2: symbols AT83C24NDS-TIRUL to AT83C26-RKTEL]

## AT83C24NDS-TIRUL
designator U?
Smart Card Reader Interface with Power Management, 3V to 5.5V, 28-Pin SOIC Pkg, Industrial, Tape and Reel, Pb-Free
footprint SO28_N (SOIC, 28-Leads, Body 17.9x7.5mm, Pitch 1.27mm, IPC Medium Density)
footprint SO28_L (SOIC, 28-Leads, Body 17.9x7.5mm, Pitch 1.27mm, IPC High Density)
footprint SO28_M (SOIC, 28-Leads, Body 17.9x7.5mm, Pitch 1.27mm, IPC Low Density)
pins: 1 C8 (io), 2 DVCC (power), 3 ~{RESET} (io), 4 ~{CMDVCC} (in), 5 VSS (power), 6 VCC (power), 7 CVSS (power), 8 LI (power), 9 CVCC (power), 10 CVCCIN (power), 11 CRST (out), 12 CCLK (out), 13 NC, 14 CC4 (io), 15 CPRES (in), 16 CC8 (io), 17 CIO (io), 18 NC, 19 SDA (io), 20 SCL (io), 21 A0/3V (in), 22 A1/RST (in), 23 A2/CK (in), 24 EVCC (power), 25 I/O (io), 26 C4 (io), 27 PRES/~{INT} (oc), 28 CLK (in)

## AT83C24NDS-TIRUM
designator U?
Smart Card Reader Interface with Power Management, 4V to 5.5V, 28-Pin SOIC Pkg, Industrial, Tape and Reel, Pb-Free
footprint SO28_N (SOIC, 28-Leads, Body 17.9x7.5mm, Pitch 1.27mm, IPC Medium Density)
footprint SO28_L (SOIC, 28-Leads, Body 17.9x7.5mm, Pitch 1.27mm, IPC High Density)
footprint SO28_M (SOIC, 28-Leads, Body 17.9x7.5mm, Pitch 1.27mm, IPC Low Density)
pins: 1 C8 (io), 2 DVCC (power), 3 ~{RESET} (io), 4 ~{CMDVCC} (in), 5 VSS (power), 6 VCC (power), 7 CVSS (power), 8 LI (power), 9 CVCC (power), 10 CVCCIN (power), 11 CRST (out), 12 CCLK (out), 13 NC, 14 CC4 (io), 15 CPRES (in), 16 CC8 (io), 17 CIO (io), 18 NC, 19 SDA (io), 20 SCL (io), 21 A0/3V (in), 22 A1/RST (in), 23 A2/CK (in), 24 EVCC (power), 25 I/O (io), 26 C4 (io), 27 PRES/~{INT} (oc), 28 CLK (in)

## AT83C24NDS-TISIL
designator U?
Smart Card Reader Interface with Power Management, 3V to 5.5V, 28-Pin SOIC Pkg, Industrial, Stick
footprint SO28_N (SOIC, 28-Leads, Body 17.9x7.5mm, Pitch 1.27mm, IPC Medium Density)
footprint SO28_L (SOIC, 28-Leads, Body 17.9x7.5mm, Pitch 1.27mm, IPC High Density)
footprint SO28_M (SOIC, 28-Leads, Body 17.9x7.5mm, Pitch 1.27mm, IPC Low Density)
pins: 1 C8 (io), 2 DVCC (power), 3 ~{RESET} (io), 4 ~{CMDVCC} (in), 5 VSS (power), 6 VCC (power), 7 CVSS (power), 8 LI (power), 9 CVCC (power), 10 CVCCIN (power), 11 CRST (out), 12 CCLK (out), 13 NC, 14 CC4 (io), 15 CPRES (in), 16 CC8 (io), 17 CIO (io), 18 NC, 19 SDA (io), 20 SCL (io), 21 A0/3V (in), 22 A1/RST (in), 23 A2/CK (in), 24 EVCC (power), 25 I/O (io), 26 C4 (io), 27 PRES/~{INT} (oc), 28 CLK (in)

## AT83C24NDS-TISIM
designator U?
Smart Card Reader Interface with Power Management, 4V to 5.5V, 28-Pin SOIC Pkg, Industrial, Stick
footprint SO28_N (SOIC, 28-Leads, Body 17.9x7.5mm, Pitch 1.27mm, IPC Medium Density)
footprint SO28_L (SOIC, 28-Leads, Body 17.9x7.5mm, Pitch 1.27mm, IPC High Density)
footprint SO28_M (SOIC, 28-Leads, Body 17.9x7.5mm, Pitch 1.27mm, IPC Low Density)
pins: 1 C8 (io), 2 DVCC (power), 3 ~{RESET} (io), 4 ~{CMDVCC} (in), 5 VSS (power), 6 VCC (power), 7 CVSS (power), 8 LI (power), 9 CVCC (power), 10 CVCCIN (power), 11 CRST (out), 12 CCLK (out), 13 NC, 14 CC4 (io), 15 CPRES (in), 16 CC8 (io), 17 CIO (io), 18 NC, 19 SDA (io), 20 SCL (io), 21 A0/3V (in), 22 A1/RST (in), 23 A2/CK (in), 24 EVCC (power), 25 I/O (io), 26 C4 (io), 27 PRES/~{INT} (oc), 28 CLK (in)

## AT83C24NDS-TISUL
designator U?
Smart Card Reader Interface with Power Management, 3V to 5.5V, 28-Pin SOIC Pkg, Industrial, Stick, Pb-Free
footprint SO28_N (SOIC, 28-Leads, Body 17.9x7.5mm, Pitch 1.27mm, IPC Medium Density)
footprint SO28_L (SOIC, 28-Leads, Body 17.9x7.5mm, Pitch 1.27mm, IPC High Density)
footprint SO28_M (SOIC, 28-Leads, Body 17.9x7.5mm, Pitch 1.27mm, IPC Low Density)
pins: 1 C8 (io), 2 DVCC (power), 3 ~{RESET} (io), 4 ~{CMDVCC} (in), 5 VSS (power), 6 VCC (power), 7 CVSS (power), 8 LI (power), 9 CVCC (power), 10 CVCCIN (power), 11 CRST (out), 12 CCLK (out), 13 NC, 14 CC4 (io), 15 CPRES (in), 16 CC8 (io), 17 CIO (io), 18 NC, 19 SDA (io), 20 SCL (io), 21 A0/3V (in), 22 A1/RST (in), 23 A2/CK (in), 24 EVCC (power), 25 I/O (io), 26 C4 (io), 27 PRES/~{INT} (oc), 28 CLK (in)

## AT83C24NDS-TISUM
designator U?
Smart Card Reader Interface with Power Management, 4V to 5.5V, 28-Pin SOIC Pkg, Industrial, Stick, Pb-Free
footprint SO28_N (SOIC, 28-Leads, Body 17.9x7.5mm, Pitch 1.27mm, IPC Medium Density)
footprint SO28_L (SOIC, 28-Leads, Body 17.9x7.5mm, Pitch 1.27mm, IPC High Density)
footprint SO28_M (SOIC, 28-Leads, Body 17.9x7.5mm, Pitch 1.27mm, IPC Low Density)
pins: 1 C8 (io), 2 DVCC (power), 3 ~{RESET} (io), 4 ~{CMDVCC} (in), 5 VSS (power), 6 VCC (power), 7 CVSS (power), 8 LI (power), 9 CVCC (power), 10 CVCCIN (power), 11 CRST (out), 12 CCLK (out), 13 NC, 14 CC4 (io), 15 CPRES (in), 16 CC8 (io), 17 CIO (io), 18 NC, 19 SDA (io), 20 SCL (io), 21 A0/3V (in), 22 A1/RST (in), 23 A2/CK (in), 24 EVCC (power), 25 I/O (io), 26 C4 (io), 27 PRES/~{INT} (oc), 28 CLK (in)

## AT83C26-PLRUL
designator U?
Multiple Smart Card Reader Interface With Power Management, Industrial, 48-Pin QFN Pkg, Tape and Reel, Pb-Free
footprint VQFN48_N (QFN, 48-Leads, Body 7x7mm, Pitch 0.5mm, IPC Medium Density)
footprint VQFN48_L (QFN, 48-Leads, Body 7x7mm, Pitch 0.5mm, IPC High Density)
footprint VQFN48_M (QFN, 48-Leads, Body 7x7mm, Pitch 0.5mm, IPC Low Density)
pins: 1 CVCC3 (power), 2 CRST3/CC82 (io), 3 CCLK3 (out), 4 CIO3/CC42 (io), 5 CVCC4 (power), 6 CRST4 (out), 7 CCLK4 (out), 8 CIO4 (io), 9 CIO5 (io), 10 CCLK5 (out), 11 CRST5 (out), 12 CVCC5 (power), 13 CC81 (io), 14 CC41 (io), 15 CIO1 (io), 16 CCLK1 (out), 17 CRST1 (out), 18 CVCCIN1 (power), 19 CPRES1 (in), 20 CVCC1 (power), 21 CVCC1 (power), 22 LIA (power), 23 CVSS1 (power), 24 VCC (power), 25 VSS (power), 26 BYPASS (in), 27 SDA (io), 28 SCL (io), 29 IO2 (io), 30 IO1 (io), 31 AUX2 (io), 32 AUX1 (io), 33 A1/RST (in), 34 A2/CK (in), 35 CLK (in), 36 INT, 37 EVCC (power), 38 CVSSB (power), 39 LIB (power), 40 CVCCB (power), 41 CVCCB (power), 42 ~{RESET} (io), 43 CPRES2 (in), 44 CVCCINB (power), 45 CVCC2 (power), 46 CRST2 (out), 47 CCLK2 (out), 48 CIO2 (io), 49 Thermal Pad (power)

## AT83C26-PLTEL
designator U?
Multiple Smart Card Reader Interface With Power Management, 25 degC, 48-Pin QFN Pkg, Tray
footprint VQFN48_N (QFN, 48-Leads, Body 7x7mm, Pitch 0.5mm, IPC Medium Density)
footprint VQFN48_L (QFN, 48-Leads, Body 7x7mm, Pitch 0.5mm, IPC High Density)
footprint VQFN48_M (QFN, 48-Leads, Body 7x7mm, Pitch 0.5mm, IPC Low Density)
pins: 1 CVCC3 (power), 2 CRST3/CC82 (io), 3 CCLK3 (out), 4 CIO3/CC42 (io), 5 CVCC4 (power), 6 CRST4 (out), 7 CCLK4 (out), 8 CIO4 (io), 9 CIO5 (io), 10 CCLK5 (out), 11 CRST5 (out), 12 CVCC5 (power), 13 CC81 (io), 14 CC41 (io), 15 CIO1 (io), 16 CCLK1 (out), 17 CRST1 (out), 18 CVCCIN1 (power), 19 CPRES1 (in), 20 CVCC1 (power), 21 CVCC1 (power), 22 LIA (power), 23 CVSS1 (power), 24 VCC (power), 25 VSS (power), 26 BYPASS (in), 27 SDA (io), 28 SCL (io), 29 IO2 (io), 30 IO1 (io), 31 AUX2 (io), 32 AUX1 (io), 33 A1/RST (in), 34 A2/CK (in), 35 CLK (in), 36 INT, 37 EVCC (power), 38 CVSSB (power), 39 LIB (power), 40 CVCCB (power), 41 CVCCB (power), 42 ~{RESET} (io), 43 CPRES2 (in), 44 CVCCINB (power), 45 CVCC2 (power), 46 CRST2 (out), 47 CCLK2 (out), 48 CIO2 (io), 49 Thermal Pad (power)

## AT83C26-PLTUL
designator U?
Multiple Smart Card Reader Interface With Power Management, Industrial, 48-Pin QFN Pkg, Tray, Pb-Free
footprint VQFN48_N (QFN, 48-Leads, Body 7x7mm, Pitch 0.5mm, IPC Medium Density)
footprint VQFN48_L (QFN, 48-Leads, Body 7x7mm, Pitch 0.5mm, IPC High Density)
footprint VQFN48_M (QFN, 48-Leads, Body 7x7mm, Pitch 0.5mm, IPC Low Density)
pins: 1 CVCC3 (power), 2 CRST3/CC82 (io), 3 CCLK3 (out), 4 CIO3/CC42 (io), 5 CVCC4 (power), 6 CRST4 (out), 7 CCLK4 (out), 8 CIO4 (io), 9 CIO5 (io), 10 CCLK5 (out), 11 CRST5 (out), 12 CVCC5 (power), 13 CC81 (io), 14 CC41 (io), 15 CIO1 (io), 16 CCLK1 (out), 17 CRST1 (out), 18 CVCCIN1 (power), 19 CPRES1 (in), 20 CVCC1 (power), 21 CVCC1 (power), 22 LIA (power), 23 CVSS1 (power), 24 VCC (power), 25 VSS (power), 26 BYPASS (in), 27 SDA (io), 28 SCL (io), 29 IO2 (io), 30 IO1 (io), 31 AUX2 (io), 32 AUX1 (io), 33 A1/RST (in), 34 A2/CK (in), 35 CLK (in), 36 INT, 37 EVCC (power), 38 CVSSB (power), 39 LIB (power), 40 CVCCB (power), 41 CVCCB (power), 42 ~{RESET} (io), 43 CPRES2 (in), 44 CVCCINB (power), 45 CVCC2 (power), 46 CRST2 (out), 47 CCLK2 (out), 48 CIO2 (io), 49 Thermal Pad (power)

## AT83C26-RKRUL
designator U?
Multiple Smart Card Reader Interface With Power Management, Industrial, 48-Pin QFP Pkg, Tape and Reel, Pb-Free
footprint 48A_N (Thin QFP, 48-Leads, Body 7x7mm, Pitch 0.5mm, IPC Medium Density)
footprint 48A_L (Thin QFP, 48-Leads, Body 7x7mm, Pitch 0.5mm, IPC High Density)
footprint 48A_M (Thin QFP, 48-Leads, Body 7x7mm, Pitch 0.5mm, IPC Low Density)
pins: 1 CVCC3 (power), 2 CRST3/CC82 (io), 3 CCLK3 (out), 4 CIO3/CC42 (io), 5 CVCC4 (power), 6 CRST4 (out), 7 CCLK4 (out), 8 CIO4 (io), 9 CIO5 (io), 10 CCLK5 (out), 11 CRST5 (out), 12 CVCC5 (power), 13 CC81 (io), 14 CC41 (io), 15 CIO1 (io), 16 CCLK1 (out), 17 CRST1 (out), 18 CVCCIN1 (power), 19 CPRES1 (in), 20 CVCC1 (power), 21 CVCC1 (power), 22 LIA (power), 23 CVSS1 (power), 24 VCC (power), 25 VSS (power), 26 BYPASS (in), 27 SDA (io), 28 SCL (io), 29 IO2 (io), 30 IO1 (io), 31 AUX2 (io), 32 AUX1 (io), 33 A1/RST (in), 34 A2/CK (in), 35 CLK (in), 36 INT, 37 EVCC (power), 38 CVSSB (power), 39 LIB (power), 40 CVCCB (power), 41 CVCCB (power), 42 ~{RESET} (io), 43 CPRES2 (in), 44 CVCCINB (power), 45 CVCC2 (power), 46 CRST2 (out), 47 CCLK2 (out), 48 CIO2 (io)

## AT83C26-RKTEL
designator U?
Multiple Smart Card Reader Interface With Power Management, 25 degC, 48-Pin QFP Pkg, Tray
footprint 48A_N (Thin QFP, 48-Leads, Body 7x7mm, Pitch 0.5mm, IPC Medium Density)
footprint 48A_L (Thin QFP, 48-Leads, Body 7x7mm, Pitch 0.5mm, IPC High Density)
footprint 48A_M (Thin QFP, 48-Leads, Body 7x7mm, Pitch 0.5mm, IPC Low Density)
pins: 1 CVCC3 (power), 2 CRST3/CC82 (io), 3 CCLK3 (out), 4 CIO3/CC42 (io), 5 CVCC4 (power), 6 CRST4 (out), 7 CCLK4 (out), 8 CIO4 (io), 9 CIO5 (io), 10 CCLK5 (out), 11 CRST5 (out), 12 CVCC5 (power), 13 CC81 (io), 14 CC41 (io), 15 CIO1 (io), 16 CCLK1 (out), 17 CRST1 (out), 18 CVCCIN1 (power), 19 CPRES1 (in), 20 CVCC1 (power), 21 CVCC1 (power), 22 LIA (power), 23 CVSS1 (power), 24 VCC (power), 25 VSS (power), 26 BYPASS (in), 27 SDA (io), 28 SCL (io), 29 IO2 (io), 30 IO1 (io), 31 AUX2 (io), 32 AUX1 (io), 33 A1/RST (in), 34 A2/CK (in), 35 CLK (in), 36 INT, 37 EVCC (power), 38 CVSSB (power), 39 LIB (power), 40 CVCCB (power), 41 CVCCB (power), 42 ~{RESET} (io), 43 CPRES2 (in), 44 CVCCINB (power), 45 CVCC2 (power), 46 CRST2 (out), 47 CCLK2 (out), 48 CIO2 (io)

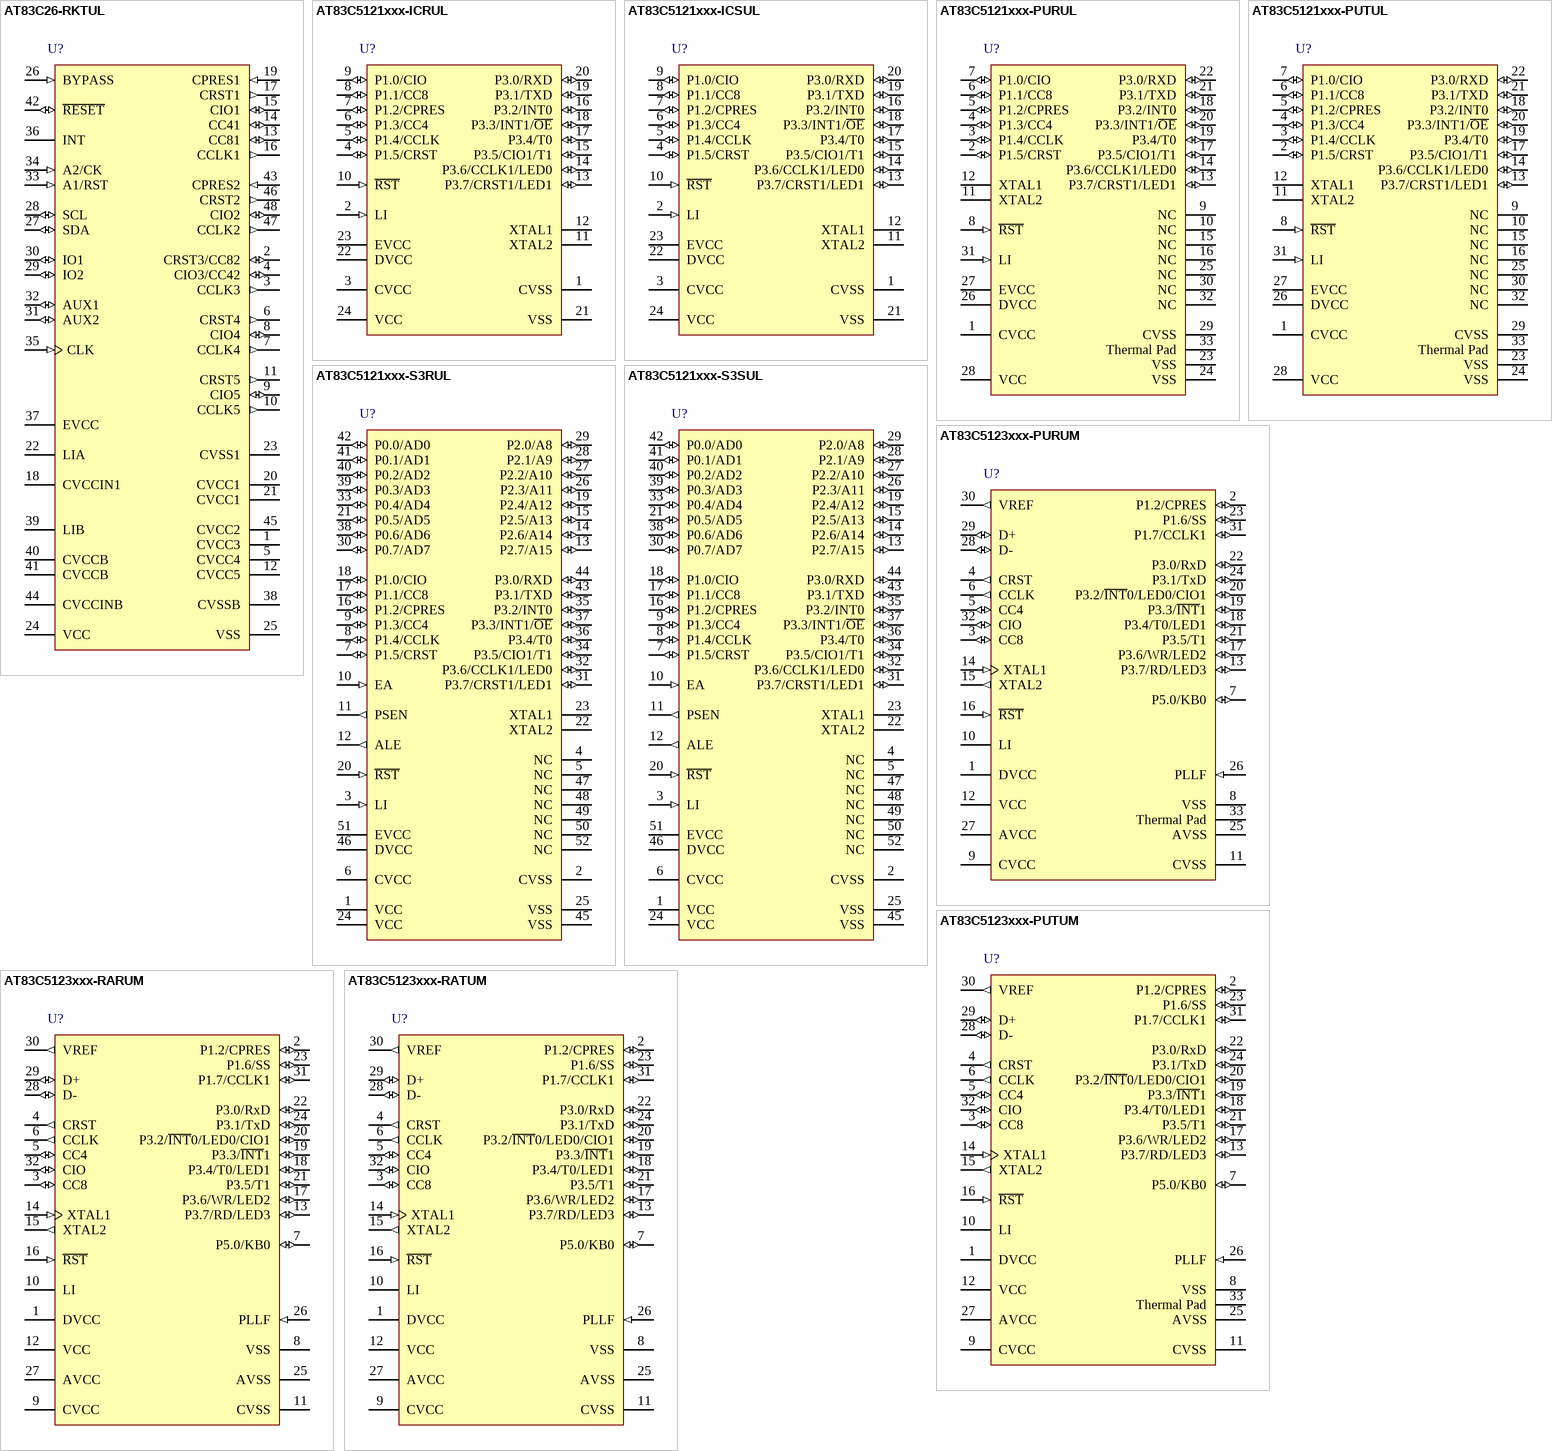
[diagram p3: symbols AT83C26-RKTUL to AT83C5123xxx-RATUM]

## AT83C26-RKTUL
designator U?
Multiple Smart Card Reader Interface With Power Management, Industrial, 48-Pin QFP Pkg, Tray, Pb-Free
footprint 48A_N (Thin QFP, 48-Leads, Body 7x7mm, Pitch 0.5mm, IPC Medium Density)
footprint 48A_L (Thin QFP, 48-Leads, Body 7x7mm, Pitch 0.5mm, IPC High Density)
footprint 48A_M (Thin QFP, 48-Leads, Body 7x7mm, Pitch 0.5mm, IPC Low Density)
pins: 1 CVCC3 (power), 2 CRST3/CC82 (io), 3 CCLK3 (out), 4 CIO3/CC42 (io), 5 CVCC4 (power), 6 CRST4 (out), 7 CCLK4 (out), 8 CIO4 (io), 9 CIO5 (io), 10 CCLK5 (out), 11 CRST5 (out), 12 CVCC5 (power), 13 CC81 (io), 14 CC41 (io), 15 CIO1 (io), 16 CCLK1 (out), 17 CRST1 (out), 18 CVCCIN1 (power), 19 CPRES1 (in), 20 CVCC1 (power), 21 CVCC1 (power), 22 LIA (power), 23 CVSS1 (power), 24 VCC (power), 25 VSS (power), 26 BYPASS (in), 27 SDA (io), 28 SCL (io), 29 IO2 (io), 30 IO1 (io), 31 AUX2 (io), 32 AUX1 (io), 33 A1/RST (in), 34 A2/CK (in), 35 CLK (in), 36 INT, 37 EVCC (power), 38 CVSSB (power), 39 LIB (power), 40 CVCCB (power), 41 CVCCB (power), 42 ~{RESET} (io), 43 CPRES2 (in), 44 CVCCINB (power), 45 CVCC2 (power), 46 CRST2 (out), 47 CCLK2 (out), 48 CIO2 (io)

## AT83C5121xxx-ICRUL
designator U?
8-bit Microcontroller with Multiprotocol Smart Card Interface, Industrial, 24-Pin SOIC Pkg, Tape and Reel, Pb-Free
footprint SSOP24_N (SOP, 24-Leads, Body 8.2x5.3mm, Pitch 0.65mm, IPC Medium Density)
footprint SSOP24_L (SOP, 24-Leads, Body 8.2x5.3mm, Pitch 0.65mm, IPC High Density)
footprint SSOP24_M (SOP, 24-Leads, Body 8.2x5.3mm, Pitch 0.65mm, IPC Low Density)
pins: 1 CVSS (power), 2 LI (in), 3 CVCC (power), 4 P1.5/CRST (io), 5 P1.4/CCLK (io), 6 P1.3/CC4 (io), 7 P1.2/CPRES (io), 8 P1.1/CC8 (io), 9 P1.0/CIO (io), 10 ~{RST} (in), 11 XTAL2, 12 XTAL1, 13 P3.7/CRST1/LED1 (io), 14 P3.6/CCLK1/LED0 (io), 15 P3.5/CIO1/T1 (io), 16 P3.2/INT0 (io), 17 P3.4/T0 (io), 18 P3.3/INT1/~{OE} (io), 19 P3.1/TXD (io), 20 P3.0/RXD (io), 21 VSS (power), 22 DVCC (power), 23 EVCC (power), 24 VCC (power)

## AT83C5121xxx-ICSUL
designator U?
8-bit Microcontroller with Multiprotocol Smart Card Interface, Industrial, 24-Pin SOIC Pkg, Stick, Pb-Free
footprint SSOP24_N (SOP, 24-Leads, Body 8.2x5.3mm, Pitch 0.65mm, IPC Medium Density)
footprint SSOP24_L (SOP, 24-Leads, Body 8.2x5.3mm, Pitch 0.65mm, IPC High Density)
footprint SSOP24_M (SOP, 24-Leads, Body 8.2x5.3mm, Pitch 0.65mm, IPC Low Density)
pins: 1 CVSS (power), 2 LI (in), 3 CVCC (power), 4 P1.5/CRST (io), 5 P1.4/CCLK (io), 6 P1.3/CC4 (io), 7 P1.2/CPRES (io), 8 P1.1/CC8 (io), 9 P1.0/CIO (io), 10 ~{RST} (in), 11 XTAL2, 12 XTAL1, 13 P3.7/CRST1/LED1 (io), 14 P3.6/CCLK1/LED0 (io), 15 P3.5/CIO1/T1 (io), 16 P3.2/INT0 (io), 17 P3.4/T0 (io), 18 P3.3/INT1/~{OE} (io), 19 P3.1/TXD (io), 20 P3.0/RXD (io), 21 VSS (power), 22 DVCC (power), 23 EVCC (power), 24 VCC (power)

## AT83C5121xxx-PURUL
designator U?
8-bit Microcontroller with Multiprotocol Smart Card Interface, Industrial, 32-Pin QFN Pkg, Tray, Pb-Free
footprint QFN32_N (QFN, 32-Leads, Body 7x7 mm, Pitch 0.65mm, IPC Medium Density)
footprint QFN32_L (QFN, 32-Leads, Body 7x7 mm, Pitch 0.65mm, IPC High Density)
footprint QFN32_M (QFN, 32-Leads, Body 7x7 mm, Pitch 0.65mm, IPC Low Density)
pins: 1 CVCC (power), 2 P1.5/CRST (io), 3 P1.4/CCLK (io), 4 P1.3/CC4 (io), 5 P1.2/CPRES (io), 6 P1.1/CC8 (io), 7 P1.0/CIO (io), 8 ~{RST} (in), 9 NC, 10 NC, 11 XTAL2, 12 XTAL1, 13 P3.7/CRST1/LED1 (io), 14 P3.6/CCLK1/LED0 (io), 15 NC, 16 NC, 17 P3.5/CIO1/T1 (io), 18 P3.2/INT0 (io), 19 P3.4/T0 (io), 20 P3.3/INT1/~{OE} (io), 21 P3.1/TXD (io), 22 P3.0/RXD (io), 23 VSS (power), 24 VSS (power), 25 NC, 26 DVCC (power), 27 EVCC (power), 28 VCC (power), 29 CVSS (power), 30 NC, 31 LI (in), 32 NC, 33 Thermal Pad (power)

## AT83C5121xxx-PUTUL
designator U?
8-bit Microcontroller with Multiprotocol Smart Card Interface, Industrial, 32-Pin QFN Pkg, Tray, Pb-Free
footprint QFN32_N (QFN, 32-Leads, Body 7x7 mm, Pitch 0.65mm, IPC Medium Density)
footprint QFN32_L (QFN, 32-Leads, Body 7x7 mm, Pitch 0.65mm, IPC High Density)
footprint QFN32_M (QFN, 32-Leads, Body 7x7 mm, Pitch 0.65mm, IPC Low Density)
pins: 1 CVCC (power), 2 P1.5/CRST (io), 3 P1.4/CCLK (io), 4 P1.3/CC4 (io), 5 P1.2/CPRES (io), 6 P1.1/CC8 (io), 7 P1.0/CIO (io), 8 ~{RST} (in), 9 NC, 10 NC, 11 XTAL2, 12 XTAL1, 13 P3.7/CRST1/LED1 (io), 14 P3.6/CCLK1/LED0 (io), 15 NC, 16 NC, 17 P3.5/CIO1/T1 (io), 18 P3.2/INT0 (io), 19 P3.4/T0 (io), 20 P3.3/INT1/~{OE} (io), 21 P3.1/TXD (io), 22 P3.0/RXD (io), 23 VSS (power), 24 VSS (power), 25 NC, 26 DVCC (power), 27 EVCC (power), 28 VCC (power), 29 CVSS (power), 30 NC, 31 LI (in), 32 NC, 33 Thermal Pad (power)

## AT83C5121xxx-S3RUL
designator U?
8-bit Microcontroller with Multiprotocol Smart Card Interface, Industrial, 52-Pin LCC Pkg, Tape and Reel, Pb-Free; Note: Contact Atmel for availability
footprint PLCC52_N (Leaded Chip Carrier, 52-Leads, Body 19x19mm, Pitch 1.27mm, IPC Medium Density)
footprint PLCC52_L (Leaded Chip Carrier, 52-Leads, Body 19x19mm, Pitch 1.27mm, IPC High Density)
footprint PLCC52_M (Leaded Chip Carrier, 52-Leads, Body 19x19mm, Pitch 1.27mm, IPC Low Density)
pins: 1 VCC (power), 2 CVSS (power), 3 LI (in), 4 NC, 5 NC, 6 CVCC (power), 7 P1.5/CRST (io), 8 P1.4/CCLK (io), 9 P1.3/CC4 (io), 10 EA (in), 11 PSEN (out), 12 ALE (out), 13 P2.7/A15 (io), 14 P2.6/A14 (io), 15 P2.5/A13 (io), 16 P1.2/CPRES (io), 17 P1.1/CC8 (io), 18 P1.0/CIO (io), 19 P2.4/A12 (io), 20 ~{RST} (in), 21 P0.5/AD5 (io), 22 XTAL2, 23 XTAL1, 24 VCC (power), 25 VSS (power), 26 P2.3/A11 (io), 27 P2.2/A10 (io), 28 P2.1/A9 (io), 29 P2.0/A8 (io), 30 P0.7/AD7 (io), 31 P3.7/CRST1/LED1 (io), 32 P3.6/CCLK1/LED0 (io), 33 P0.4/AD4 (io), 34 P3.5/CIO1/T1 (io), 35 P3.2/INT0 (io), 36 P3.4/T0 (io), 37 P3.3/INT1/~{OE} (io), 38 P0.6/AD6 (io), 39 P0.3/AD3 (io), 40 P0.2/AD2 (io), 41 P0.1/AD1 (io), 42 P0.0/AD0 (io), 43 P3.1/TXD (io), 44 P3.0/RXD (io), 45 VSS (power), 46 DVCC (power), 47 NC, 48 NC, 49 NC, 50 NC, 51 EVCC (power), 52 NC

## AT83C5121xxx-S3SUL
designator U?
8-bit Microcontroller with Multiprotocol Smart Card Interface, Industrial, 52-Pin LCC Pkg, Stick, Pb-Free; Note: Contact Atmel for availability
footprint PLCC52_N (Leaded Chip Carrier, 52-Leads, Body 19x19mm, Pitch 1.27mm, IPC Medium Density)
footprint PLCC52_L (Leaded Chip Carrier, 52-Leads, Body 19x19mm, Pitch 1.27mm, IPC High Density)
footprint PLCC52_M (Leaded Chip Carrier, 52-Leads, Body 19x19mm, Pitch 1.27mm, IPC Low Density)
pins: 1 VCC (power), 2 CVSS (power), 3 LI (in), 4 NC, 5 NC, 6 CVCC (power), 7 P1.5/CRST (io), 8 P1.4/CCLK (io), 9 P1.3/CC4 (io), 10 EA (in), 11 PSEN (out), 12 ALE (out), 13 P2.7/A15 (io), 14 P2.6/A14 (io), 15 P2.5/A13 (io), 16 P1.2/CPRES (io), 17 P1.1/CC8 (io), 18 P1.0/CIO (io), 19 P2.4/A12 (io), 20 ~{RST} (in), 21 P0.5/AD5 (io), 22 XTAL2, 23 XTAL1, 24 VCC (power), 25 VSS (power), 26 P2.3/A11 (io), 27 P2.2/A10 (io), 28 P2.1/A9 (io), 29 P2.0/A8 (io), 30 P0.7/AD7 (io), 31 P3.7/CRST1/LED1 (io), 32 P3.6/CCLK1/LED0 (io), 33 P0.4/AD4 (io), 34 P3.5/CIO1/T1 (io), 35 P3.2/INT0 (io), 36 P3.4/T0 (io), 37 P3.3/INT1/~{OE} (io), 38 P0.6/AD6 (io), 39 P0.3/AD3 (io), 40 P0.2/AD2 (io), 41 P0.1/AD1 (io), 42 P0.0/AD0 (io), 43 P3.1/TXD (io), 44 P3.0/RXD (io), 45 VSS (power), 46 DVCC (power), 47 NC, 48 NC, 49 NC, 50 NC, 51 EVCC (power), 52 NC

## AT83C5123xxx-PURUM
designator U?
C51 Microcontroller with USB and Smart Card Reader Interfaces, 30K ROM, Industrial, 32-Pin QFN Pkg, Tape and Reel
footprint QFN32_N (QFN, 32-Leads, Body 7x7 mm, Pitch 0.65mm, IPC Medium Density)
footprint QFN32_L (QFN, 32-Leads, Body 7x7 mm, Pitch 0.65mm, IPC High Density)
footprint QFN32_M (QFN, 32-Leads, Body 7x7 mm, Pitch 0.65mm, IPC Low Density)
pins: 1 DVCC (power), 2 P1.2/CPRES (io), 3 CC8 (io), 4 CRST (out), 5 CC4 (io), 6 CCLK (out), 7 P5.0/KB0 (io), 8 VSS (power), 9 CVCC (power), 10 LI (power), 11 CVSS (power), 12 VCC (power), 13 P3.7/RD/LED3 (io), 14 XTAL1 (in), 15 XTAL2 (out), 16 ~{RST} (in), 17 P3.6/WR/LED2 (io), 18 P3.4/T0/LED1 (io), 19 P3.3/~{INT}1 (io), 20 P3.2/~{INT}0/LED0/CIO1 (io), 21 P3.5/T1 (io), 22 P3.0/RxD (io), 23 P1.6/SS (io), 24 P3.1/TxD (io), 25 AVSS (power), 26 PLLF (in), 27 AVCC (power), 28 D- (io), 29 D+ (io), 30 VREF (out), 31 P1.7/CCLK1 (io), 32 CIO (io), 33 Thermal Pad (power)

## AT83C5123xxx-PUTUM
designator U?
C51 Microcontroller with USB and Smart Card Reader Interfaces, 30K ROM, Industrial, 32-Pin QFN Pkg, Tray
footprint QFN32_N (QFN, 32-Leads, Body 7x7 mm, Pitch 0.65mm, IPC Medium Density)
footprint QFN32_L (QFN, 32-Leads, Body 7x7 mm, Pitch 0.65mm, IPC High Density)
footprint QFN32_M (QFN, 32-Leads, Body 7x7 mm, Pitch 0.65mm, IPC Low Density)
pins: 1 DVCC (power), 2 P1.2/CPRES (io), 3 CC8 (io), 4 CRST (out), 5 CC4 (io), 6 CCLK (out), 7 P5.0/KB0 (io), 8 VSS (power), 9 CVCC (power), 10 LI (power), 11 CVSS (power), 12 VCC (power), 13 P3.7/RD/LED3 (io), 14 XTAL1 (in), 15 XTAL2 (out), 16 ~{RST} (in), 17 P3.6/WR/LED2 (io), 18 P3.4/T0/LED1 (io), 19 P3.3/~{INT}1 (io), 20 P3.2/~{INT}0/LED0/CIO1 (io), 21 P3.5/T1 (io), 22 P3.0/RxD (io), 23 P1.6/SS (io), 24 P3.1/TxD (io), 25 AVSS (power), 26 PLLF (in), 27 AVCC (power), 28 D- (io), 29 D+ (io), 30 VREF (out), 31 P1.7/CCLK1 (io), 32 CIO (io), 33 Thermal Pad (power)

## AT83C5123xxx-RARUM
designator U?
C51 Microcontroller with USB and Smart Card Reader Interfaces, 30K ROM, Industrial, 32-Pin QFP Pkg, Tape and Reel
footprint LQFP32_N (Thin QFP, 32-Leads, Body 7x7mm, Pitch 0.8mm, IPC Medium Density)
footprint LQFP32_L (Thin QFP, 32-Leads, Body 7x7mm, Pitch 0.8mm, IPC High Density)
footprint LQFP32_M (Thin QFP, 32-Leads, Body 7x7mm, Pitch 0.8mm, IPC Low Density)
pins: 1 DVCC (power), 2 P1.2/CPRES (io), 3 CC8 (io), 4 CRST (out), 5 CC4 (io), 6 CCLK (out), 7 P5.0/KB0 (io), 8 VSS (power), 9 CVCC (power), 10 LI (power), 11 CVSS (power), 12 VCC (power), 13 P3.7/RD/LED3 (io), 14 XTAL1 (in), 15 XTAL2 (out), 16 ~{RST} (in), 17 P3.6/WR/LED2 (io), 18 P3.4/T0/LED1 (io), 19 P3.3/~{INT}1 (io), 20 P3.2/~{INT}0/LED0/CIO1 (io), 21 P3.5/T1 (io), 22 P3.0/RxD (io), 23 P1.6/SS (io), 24 P3.1/TxD (io), 25 AVSS (power), 26 PLLF (in), 27 AVCC (power), 28 D- (io), 29 D+ (io), 30 VREF (out), 31 P1.7/CCLK1 (io), 32 CIO (io)

## AT83C5123xxx-RATUM
designator U?
C51 Microcontroller with USB and Smart Card Reader Interfaces, 30K ROM, Industrial, 32-Pin QFP Pkg, Tray
footprint LQFP32_N (Thin QFP, 32-Leads, Body 7x7mm, Pitch 0.8mm, IPC Medium Density)
footprint LQFP32_L (Thin QFP, 32-Leads, Body 7x7mm, Pitch 0.8mm, IPC High Density)
footprint LQFP32_M (Thin QFP, 32-Leads, Body 7x7mm, Pitch 0.8mm, IPC Low Density)
pins: 1 DVCC (power), 2 P1.2/CPRES (io), 3 CC8 (io), 4 CRST (out), 5 CC4 (io), 6 CCLK (out), 7 P5.0/KB0 (io), 8 VSS (power), 9 CVCC (power), 10 LI (power), 11 CVSS (power), 12 VCC (power), 13 P3.7/RD/LED3 (io), 14 XTAL1 (in), 15 XTAL2 (out), 16 ~{RST} (in), 17 P3.6/WR/LED2 (io), 18 P3.4/T0/LED1 (io), 19 P3.3/~{INT}1 (io), 20 P3.2/~{INT}0/LED0/CIO1 (io), 21 P3.5/T1 (io), 22 P3.0/RxD (io), 23 P1.6/SS (io), 24 P3.1/TxD (io), 25 AVSS (power), 26 PLLF (in), 27 AVCC (power), 28 D- (io), 29 D+ (io), 30 VREF (out), 31 P1.7/CCLK1 (io), 32 CIO (io)

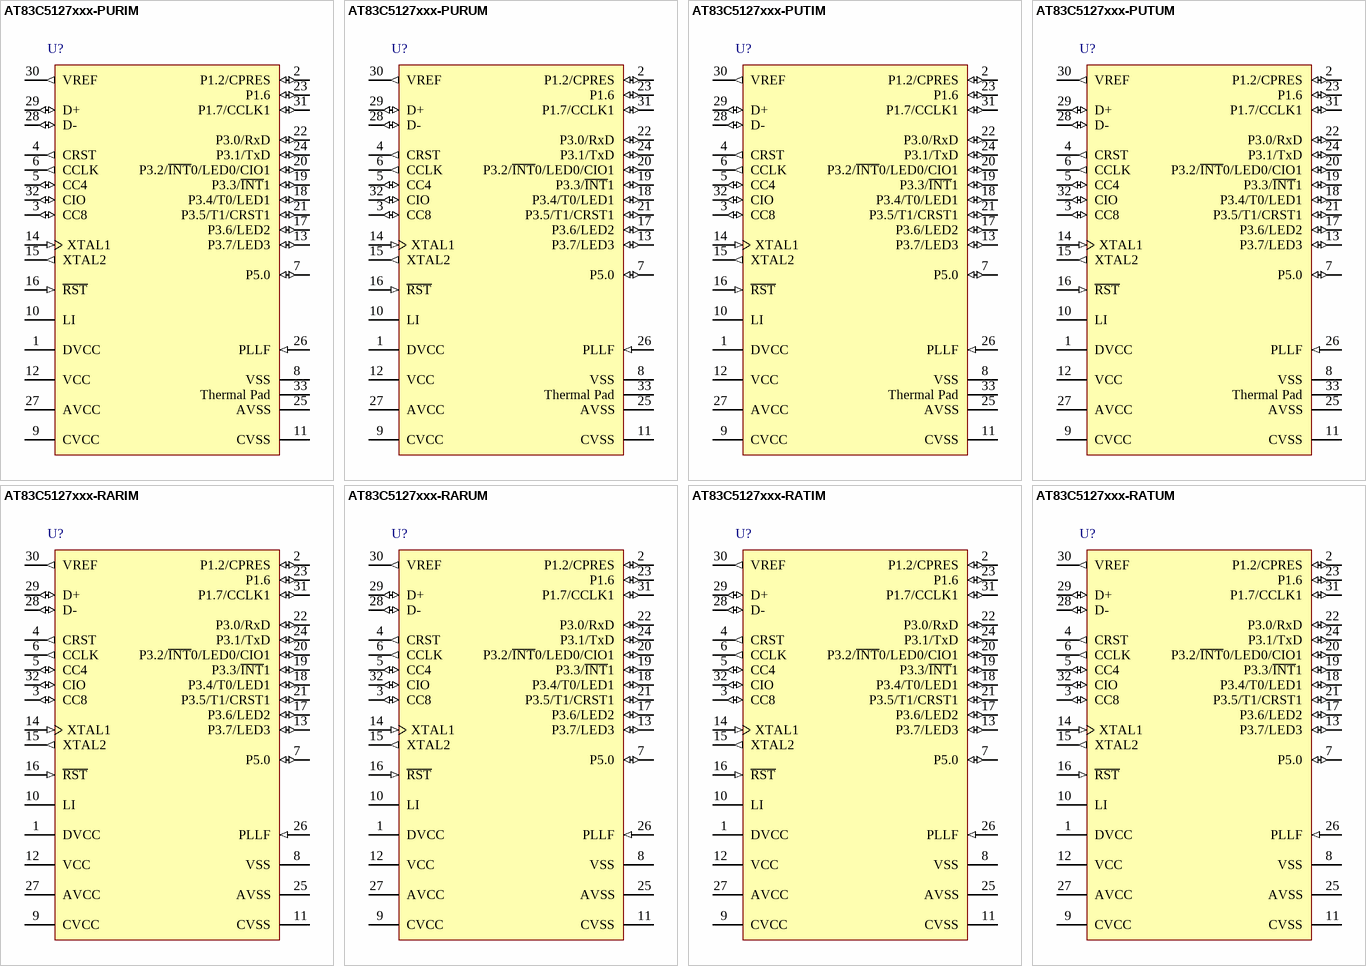
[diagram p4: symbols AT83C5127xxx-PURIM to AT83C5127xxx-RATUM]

## AT83C5127xxx-PURIM
designator U?
C51 Microcontroller with USB and Smart Card Reader Interfaces, Industrial, 32-Pin QFN Pkg, Tape and Reel
footprint QFN32_N (QFN, 32-Leads, Body 7x7 mm, Pitch 0.65mm, IPC Medium Density)
footprint QFN32_L (QFN, 32-Leads, Body 7x7 mm, Pitch 0.65mm, IPC High Density)
footprint QFN32_M (QFN, 32-Leads, Body 7x7 mm, Pitch 0.65mm, IPC Low Density)
pins: 1 DVCC (power), 2 P1.2/CPRES (io), 3 CC8 (io), 4 CRST (out), 5 CC4 (io), 6 CCLK (out), 7 P5.0 (io), 8 VSS (power), 9 CVCC (power), 10 LI (power), 11 CVSS (power), 12 VCC (power), 13 P3.7/LED3 (io), 14 XTAL1 (in), 15 XTAL2 (out), 16 ~{RST} (in), 17 P3.6/LED2 (io), 18 P3.4/T0/LED1 (io), 19 P3.3/~{INT}1 (io), 20 P3.2/~{INT}0/LED0/CIO1 (io), 21 P3.5/T1/CRST1 (io), 22 P3.0/RxD (io), 23 P1.6 (io), 24 P3.1/TxD (io), 25 AVSS (power), 26 PLLF (in), 27 AVCC (power), 28 D- (io), 29 D+ (io), 30 VREF (out), 31 P1.7/CCLK1 (io), 32 CIO (io), 33 Thermal Pad (power)

## AT83C5127xxx-PURUM
designator U?
C51 Microcontroller with USB and Smart Card Reader Interfaces, Industrial, 32-Pin QFN Pkg, Tape and Reel, Pb-Free
footprint QFN32_N (QFN, 32-Leads, Body 7x7 mm, Pitch 0.65mm, IPC Medium Density)
footprint QFN32_L (QFN, 32-Leads, Body 7x7 mm, Pitch 0.65mm, IPC High Density)
footprint QFN32_M (QFN, 32-Leads, Body 7x7 mm, Pitch 0.65mm, IPC Low Density)
pins: 1 DVCC (power), 2 P1.2/CPRES (io), 3 CC8 (io), 4 CRST (out), 5 CC4 (io), 6 CCLK (out), 7 P5.0 (io), 8 VSS (power), 9 CVCC (power), 10 LI (power), 11 CVSS (power), 12 VCC (power), 13 P3.7/LED3 (io), 14 XTAL1 (in), 15 XTAL2 (out), 16 ~{RST} (in), 17 P3.6/LED2 (io), 18 P3.4/T0/LED1 (io), 19 P3.3/~{INT}1 (io), 20 P3.2/~{INT}0/LED0/CIO1 (io), 21 P3.5/T1/CRST1 (io), 22 P3.0/RxD (io), 23 P1.6 (io), 24 P3.1/TxD (io), 25 AVSS (power), 26 PLLF (in), 27 AVCC (power), 28 D- (io), 29 D+ (io), 30 VREF (out), 31 P1.7/CCLK1 (io), 32 CIO (io), 33 Thermal Pad (power)

## AT83C5127xxx-PUTIM
designator U?
C51 Microcontroller with USB and Smart Card Reader Interfaces, Industrial, 32-Pin QFN Pkg, Tray
footprint QFN32_N (QFN, 32-Leads, Body 7x7 mm, Pitch 0.65mm, IPC Medium Density)
footprint QFN32_L (QFN, 32-Leads, Body 7x7 mm, Pitch 0.65mm, IPC High Density)
footprint QFN32_M (QFN, 32-Leads, Body 7x7 mm, Pitch 0.65mm, IPC Low Density)
pins: 1 DVCC (power), 2 P1.2/CPRES (io), 3 CC8 (io), 4 CRST (out), 5 CC4 (io), 6 CCLK (out), 7 P5.0 (io), 8 VSS (power), 9 CVCC (power), 10 LI (power), 11 CVSS (power), 12 VCC (power), 13 P3.7/LED3 (io), 14 XTAL1 (in), 15 XTAL2 (out), 16 ~{RST} (in), 17 P3.6/LED2 (io), 18 P3.4/T0/LED1 (io), 19 P3.3/~{INT}1 (io), 20 P3.2/~{INT}0/LED0/CIO1 (io), 21 P3.5/T1/CRST1 (io), 22 P3.0/RxD (io), 23 P1.6 (io), 24 P3.1/TxD (io), 25 AVSS (power), 26 PLLF (in), 27 AVCC (power), 28 D- (io), 29 D+ (io), 30 VREF (out), 31 P1.7/CCLK1 (io), 32 CIO (io), 33 Thermal Pad (power)

## AT83C5127xxx-PUTUM
designator U?
C51 Microcontroller with USB and Smart Card Reader Interfaces, Industrial, 32-Pin QFN Pkg, Tray, Pb-Free
footprint QFN32_N (QFN, 32-Leads, Body 7x7 mm, Pitch 0.65mm, IPC Medium Density)
footprint QFN32_L (QFN, 32-Leads, Body 7x7 mm, Pitch 0.65mm, IPC High Density)
footprint QFN32_M (QFN, 32-Leads, Body 7x7 mm, Pitch 0.65mm, IPC Low Density)
pins: 1 DVCC (power), 2 P1.2/CPRES (io), 3 CC8 (io), 4 CRST (out), 5 CC4 (io), 6 CCLK (out), 7 P5.0 (io), 8 VSS (power), 9 CVCC (power), 10 LI (power), 11 CVSS (power), 12 VCC (power), 13 P3.7/LED3 (io), 14 XTAL1 (in), 15 XTAL2 (out), 16 ~{RST} (in), 17 P3.6/LED2 (io), 18 P3.4/T0/LED1 (io), 19 P3.3/~{INT}1 (io), 20 P3.2/~{INT}0/LED0/CIO1 (io), 21 P3.5/T1/CRST1 (io), 22 P3.0/RxD (io), 23 P1.6 (io), 24 P3.1/TxD (io), 25 AVSS (power), 26 PLLF (in), 27 AVCC (power), 28 D- (io), 29 D+ (io), 30 VREF (out), 31 P1.7/CCLK1 (io), 32 CIO (io), 33 Thermal Pad (power)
